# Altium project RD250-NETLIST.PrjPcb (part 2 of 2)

## Sheet 5.SchDoc
size 599 x 434 mm
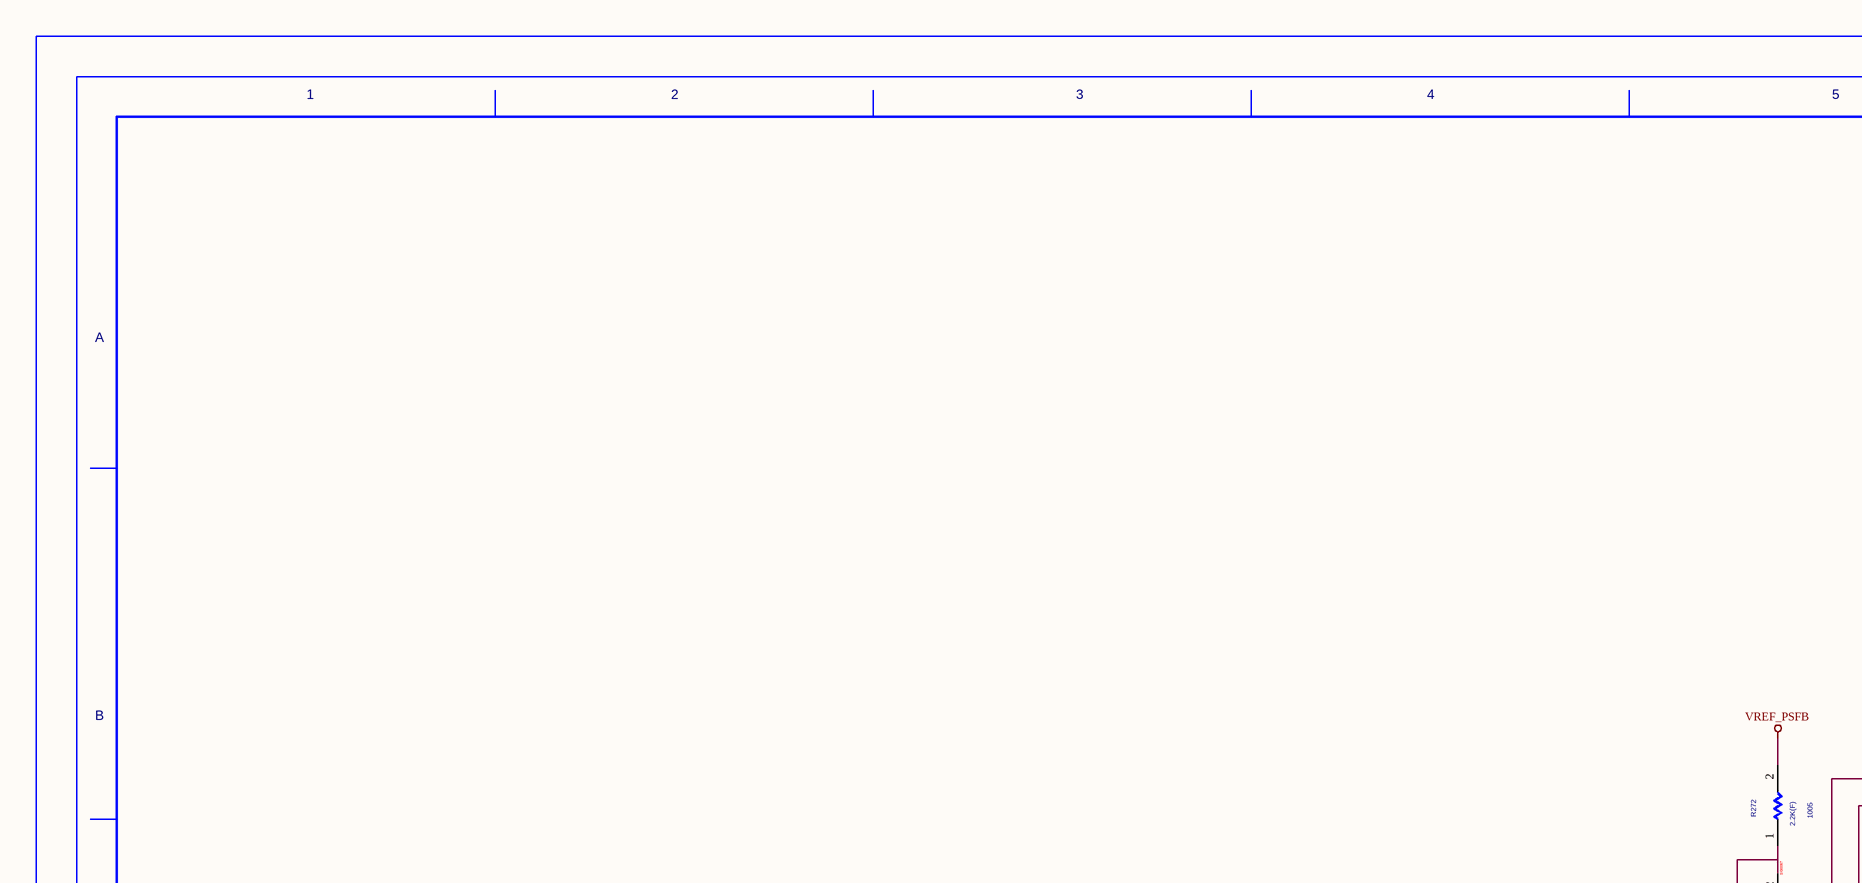
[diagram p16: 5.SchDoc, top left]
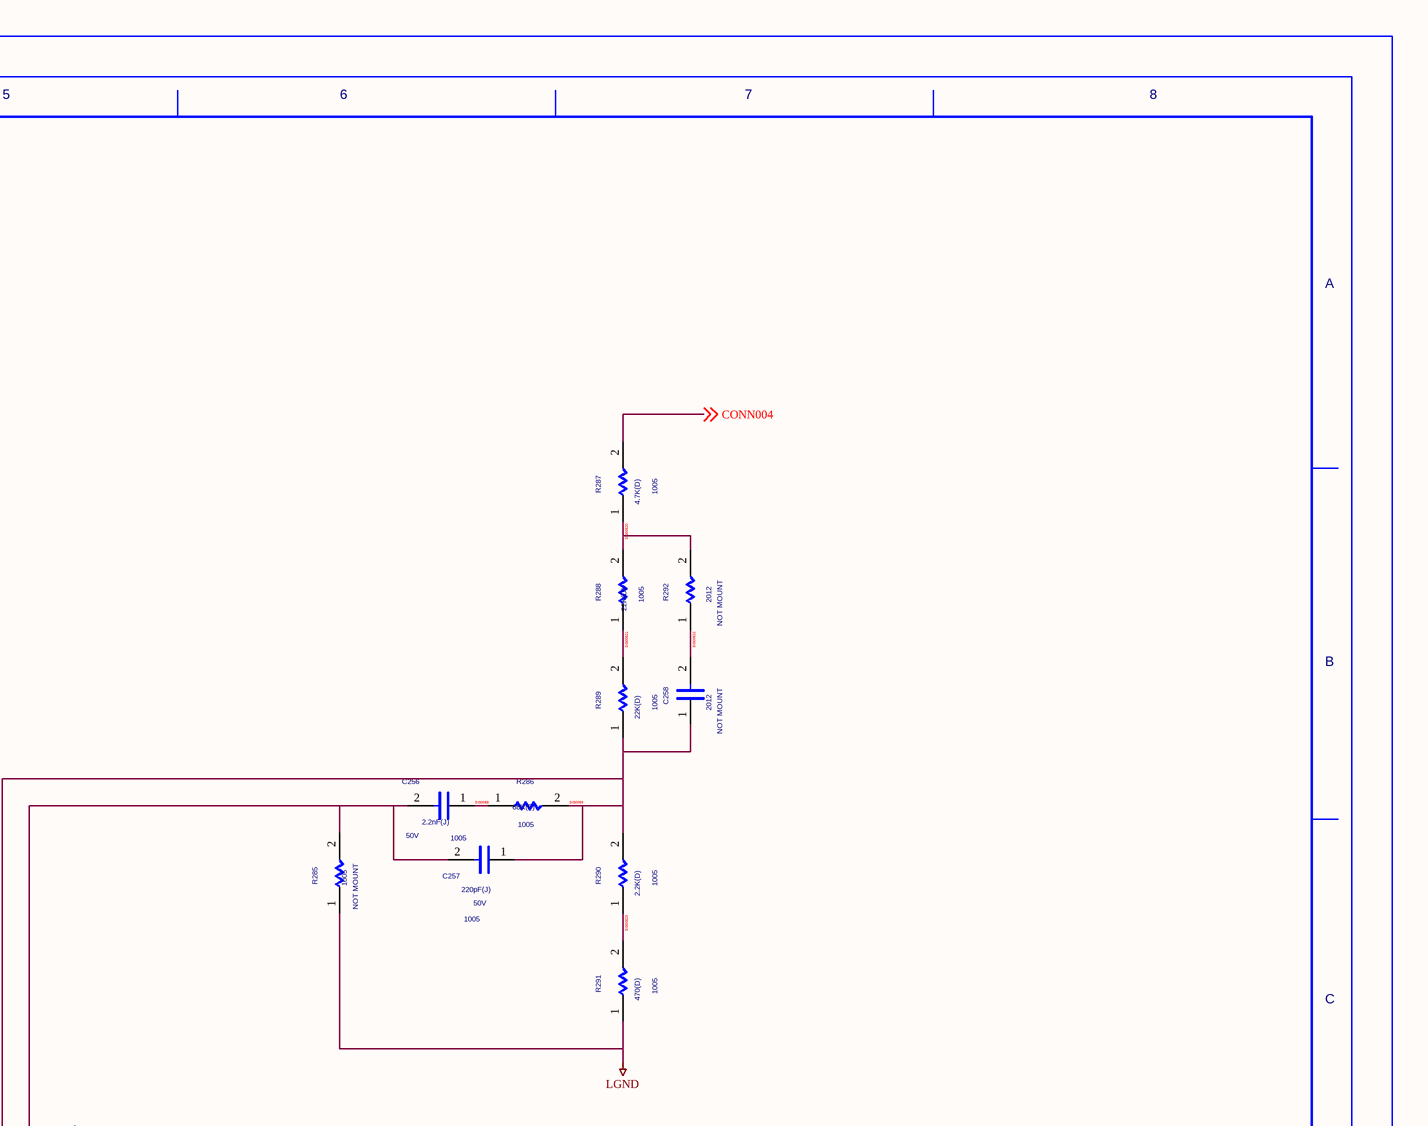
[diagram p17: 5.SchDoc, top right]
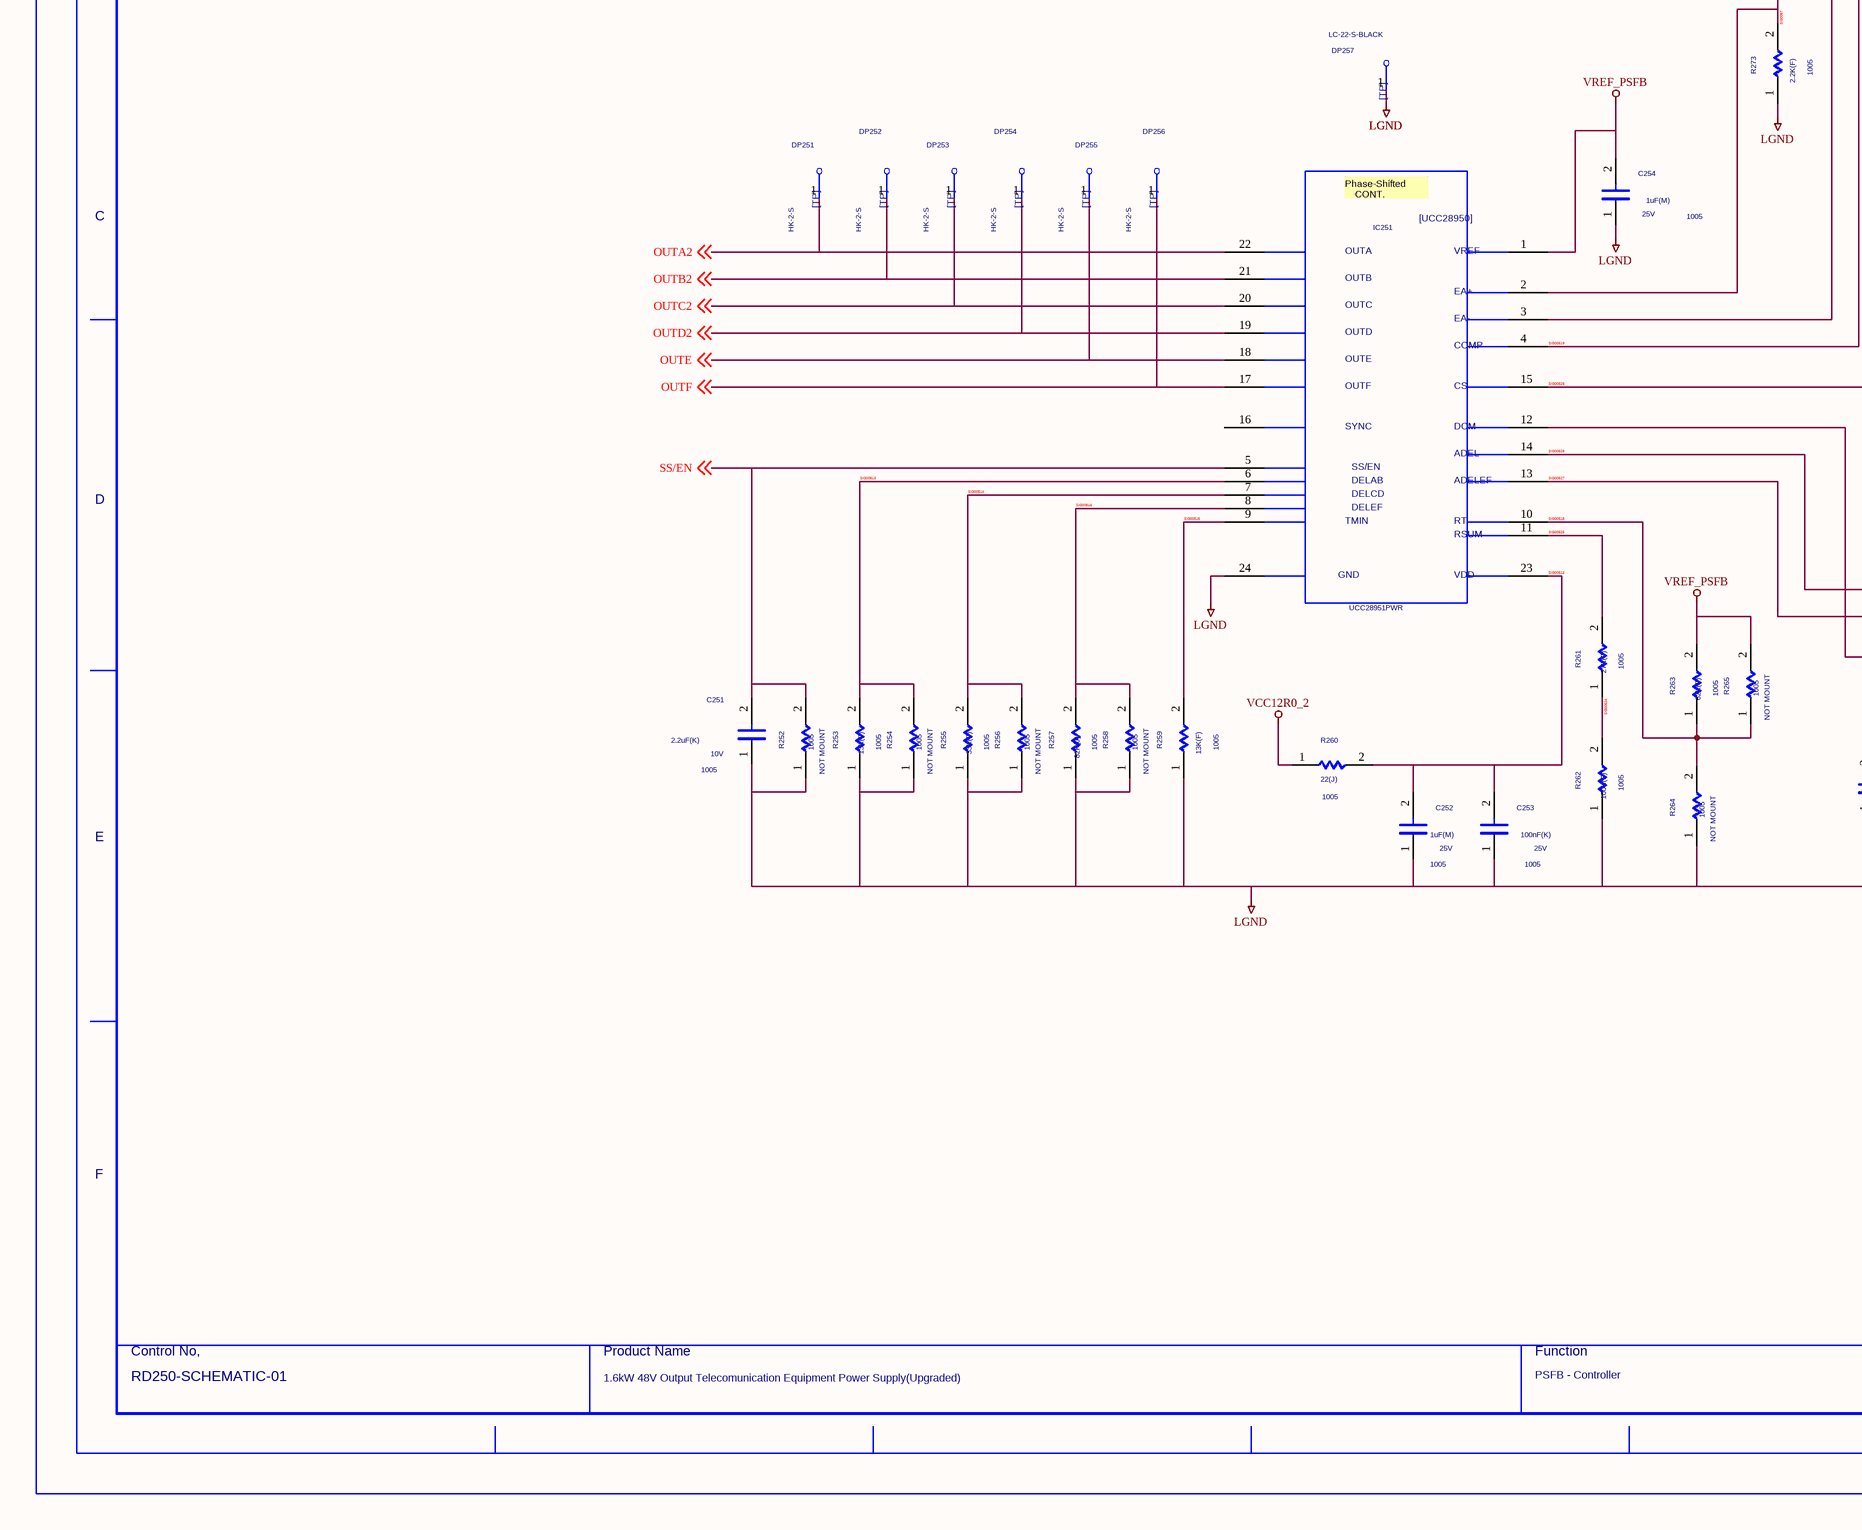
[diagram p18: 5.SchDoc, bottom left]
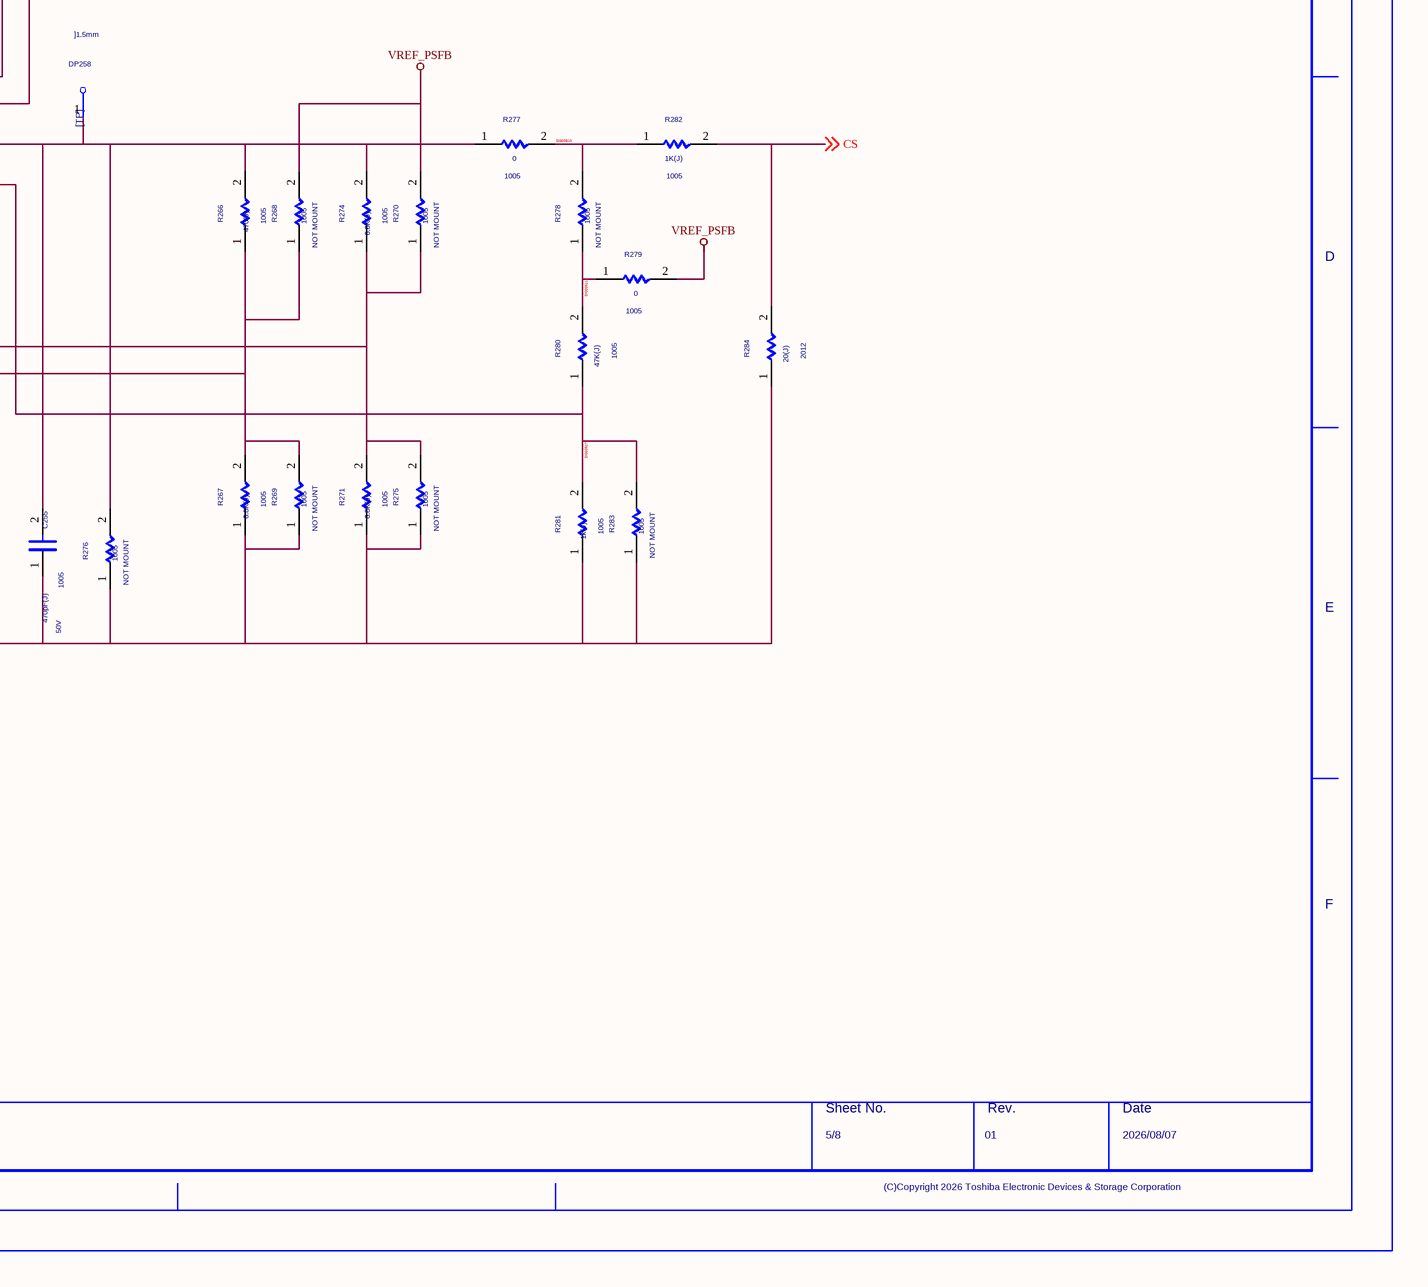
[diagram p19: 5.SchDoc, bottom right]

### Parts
(Parts that share a designator on the sheet are numbered #1, #2 ... from top to bottom, then left to right.)
C251  VAL1: 2.2uF(K)  VAL2: 10V  SIZECODESMD: 1005  (hidden comment: C)
C252  VAL1: 1uF(M)  VAL2: 25V  SIZECODESMD: 1005  (hidden comment: C)
C253  VAL1: 100nF(K)  VAL2: 25V  SIZECODESMD: 1005  (hidden comment: C)
C254  VAL1: 1uF(M)  VAL2: 25V  SIZECODESMD: 1005  (hidden comment: C)
C255  VAL1: 470pF(J)  VAL2: 50V  SIZECODESMD: 1005  (hidden comment: C)
C256  VAL1: 2.2nF(J)  VAL2: 50V  SIZECODESMD: 1005  (hidden comment: C)
C257  VAL1: 220pF(J)  VAL2: 50V  SIZECODESMD: 1005  (hidden comment: C)
C258  NOTMOUNT: NOT MOUNT  SIZECODESMD: 2012  (hidden comment: C)
DP251  VAL3: HK-2-S  (hidden comment: TP)
DP252  VAL3: HK-2-S  (hidden comment: TP)
DP253  VAL3: HK-2-S  (hidden comment: TP)
DP254  VAL3: HK-2-S  (hidden comment: TP)
DP255  VAL3: HK-2-S  (hidden comment: TP)
DP256  VAL3: HK-2-S  (hidden comment: TP)
DP257  VAL3: LC-22-S-BLACK  (hidden comment: TP)
DP258  USERCOMPTEXT1: ]1.5mm  (hidden comment: TP)
IC251  VAL3: UCC28951PWR  (hidden comment: L28950)
R252  NOTMOUNT: NOT MOUNT  SIZECODESMD: 1005  (hidden comment: R)
R253  VAL1: 13K(F)  SIZECODESMD: 1005  (hidden comment: R)
R254  NOTMOUNT: NOT MOUNT  SIZECODESMD: 1005  (hidden comment: R)
R255  VAL1: 33K(F)  SIZECODESMD: 1005  (hidden comment: R)
R256  NOTMOUNT: NOT MOUNT  SIZECODESMD: 1005  (hidden comment: R)
R257  VAL1: 82K(J)  SIZECODESMD: 1005  (hidden comment: R)
R258  NOTMOUNT: NOT MOUNT  SIZECODESMD: 1005  (hidden comment: R)
R259  VAL1: 13K(F)  SIZECODESMD: 1005  (hidden comment: R)
R260  VAL1: 22(J)  SIZECODESMD: 1005  (hidden comment: R)
R261  VAL1: 27K(F)  SIZECODESMD: 1005  (hidden comment: R)
R262  VAL1: 100K(F)  SIZECODESMD: 1005  (hidden comment: R)
R263  VAL1: 62K(F)  SIZECODESMD: 1005  (hidden comment: R)
R264  NOTMOUNT: NOT MOUNT  SIZECODESMD: 1005  (hidden comment: R)
R265  NOTMOUNT: NOT MOUNT  SIZECODESMD: 1005  (hidden comment: R)
R266  VAL1: 470(J)  SIZECODESMD: 1005  (hidden comment: R)
R267  VAL1: 6.8K(J)  SIZECODESMD: 1005  (hidden comment: R)
R268  NOTMOUNT: NOT MOUNT  SIZECODESMD: 1005  (hidden comment: R)
R269  NOTMOUNT: NOT MOUNT  SIZECODESMD: 1005  (hidden comment: R)
R270  NOTMOUNT: NOT MOUNT  SIZECODESMD: 1005  (hidden comment: R)
R271  VAL1: 6.8K(J)  SIZECODESMD: 1005  (hidden comment: R)
R272  VAL1: 2.2K(F)  SIZECODESMD: 1005  (hidden comment: R)
R273  VAL1: 2.2K(F)  SIZECODESMD: 1005  (hidden comment: R)
R274  VAL1: 6.8K(J)  SIZECODESMD: 1005  (hidden comment: R)
R275  NOTMOUNT: NOT MOUNT  SIZECODESMD: 1005  (hidden comment: R)
R276  NOTMOUNT: NOT MOUNT  SIZECODESMD: 1005  (hidden comment: R)
R277  VAL1: 0  SIZECODESMD: 1005  (hidden comment: R)
R278  NOTMOUNT: NOT MOUNT  SIZECODESMD: 1005  (hidden comment: R)
R279  VAL1: 0  SIZECODESMD: 1005  (hidden comment: R)
R280  VAL1: 47K(J)  SIZECODESMD: 1005  (hidden comment: R)
R281  VAL1: 1k(J)  SIZECODESMD: 1005  (hidden comment: R)
R282  VAL1: 1K(J)  SIZECODESMD: 1005  (hidden comment: R)
R283  NOTMOUNT: NOT MOUNT  SIZECODESMD: 1005  (hidden comment: R)
R284  VAL1: 20(J)  SIZECODESMD: 2012  (hidden comment: R)
R285  NOTMOUNT: NOT MOUNT  SIZECODESMD: 1005  (hidden comment: R)
R286  VAL1: 68K(F)  SIZECODESMD: 1005  (hidden comment: R)
R287  VAL1: 4.7K(D)  SIZECODESMD: 1005  (hidden comment: R)
R288  VAL1: 22K(D)  SIZECODESMD: 1005  (hidden comment: R)
R289  VAL1: 22K(D)  SIZECODESMD: 1005  (hidden comment: R)
R290  VAL1: 2.2K(D)  SIZECODESMD: 1005  (hidden comment: R)
R291  VAL1: 470(D)  SIZECODESMD: 1005  (hidden comment: R)
R292  NOTMOUNT: NOT MOUNT  SIZECODESMD: 2012  (hidden comment: R)
U?#5  DATE: 2026/08/07  DRAWINGNUMBER: RD250-SCHEMATIC-01  TITLE: 1.6kW 48V Output Telecomunication / Equipment Power Supply(Upgraded)  FUNCTION: PSFB - Controller  SHEETNUMBER: 5/8  REVISION: 01  (hidden comment: WAKU_A3_TDSC_PSDEV_LOCAL)

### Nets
LGND: C251.1 C252.1 C253.1 C254.1 C255.1 DP257.1 IC251.24 R252.1 R253.1 R254.1 R255.1 R256.1 R257.1 R258.1 R259.1 R262.1 R264.1 R267.1 R269.1 R271.1 R273.1 R275.1 R276.1 R281.1 R283.1 R284.1 R285.1 R291.1
VCC12R0_2: R260.1
VREF_PSFB: C254.2 IC251.1 R263.2 R265.2 R268.2 R270.2 R272.2 R279.2
CONN004: R287.2 ; off-sheet CONN004
CS: R282.2 R284.2 ; off-sheet CS
OUTA2: DP251.1 IC251.22 ; off-sheet OUTA2
OUTB2: DP252.1 IC251.21 ; off-sheet OUTB2
OUTC2: DP253.1 IC251.20 ; off-sheet OUTC2
OUTD2: DP254.1 IC251.19 ; off-sheet OUTD2
OUTE: DP255.1 IC251.18 ; off-sheet OUTE
OUTF: DP256.1 IC251.17 ; off-sheet OUTF
SIG0057: IC251.2 R272.1 R273.2
SIG0058: C256.1 R286.1
SIG0059: C257.1 C258.1 IC251.3 R286.2 R289.1 R290.2
SIG00510: R277.2 R278.2 R282.1
SIG00511: R278.1 R279.1 R280.2
SIG00512: C252.2 C253.2 IC251.23 R260.2
SIG00513: IC251.6 R253.2 R254.2
SIG00514: IC251.7 R255.2 R256.2
SIG00515: IC251.9 R259.2
SIG00516: IC251.8 R257.2 R258.2
SIG00517: IC251.12 R280.1 R281.2 R283.2
SIG00518: IC251.10 R263.1 R264.2 R265.1
SIG00519: C256.2 C257.2 IC251.4 R285.2
SIG00520: R287.1 R288.2 R292.2
SIG00521: R288.1 R289.2
SIG00522: C258.2 R292.1
SIG00523: R290.1 R291.2
SIG00524: R261.1 R262.2
SIG00525: IC251.11 R261.2
SIG00526: C255.2 DP258.1 IC251.15 R266.2 R274.2 R276.2 R277.1
SIG00527: IC251.13 R266.1 R267.2 R268.1 R269.2
SIG00528: IC251.14 R270.1 R271.2 R274.1 R275.2
SS/EN: C251.2 IC251.5 R252.2 ; off-sheet SS/EN

Not connected (* = marked no-connect by the designer): IC251 16

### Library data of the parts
C251-C255 = C_Dup1: OriginalSymbolOrigin: (2540,7620); COMP: PRT_52; MAXGCOUNT: 1; SAVECOUNT: 0
C256 = C_Dup1: SQ_PART_MODEL: CON_5.6N; OriginalSymbolOrigin: (2540,7620); COMP: PRT_52; MAXGCOUNT: 1; ADSCNVFLAG: ON; ADSCOMPONENTNAME: C_1005; SAVECOUNT: 0
C257 = C_Dup1: SQ_PART_MODEL: CON_560P; OriginalSymbolOrigin: (2540,7620); COMP: PRT_52; MAXGCOUNT: 1; ADSCNVFLAG: ON; ADSCOMPONENTNAME: C_1005; SAVECOUNT: 0
C258 = C_Dup1: OriginalSymbolOrigin: (2540,7620); COMP: C2012; CHIPSIZE: 3216; MAXGCOUNT: 1; SAVECOUNT: 0
DP251-DP256 = TP: TIME: 16:12:21; UPDATEUSER: fukuda-y; UPDATETIME: 16:18:11; SAVECOUNT: 2; SAVEAREA0: -242,-92,12810,7836; OriginalSymbolOrigin: (0,7620); COMP: PRT_44
DP257 = TP: TIME: 16:12:21; UPDATEUSER: fukuda-y; UPDATETIME: 16:18:11; SAVECOUNT: 2; SAVEAREA0: -242,-92,12810,7836; OriginalSymbolOrigin: (0,7620); COMP: PRT_34
DP258 = TP: TIME: 16:12:21; UPDATEUSER: fukuda-y; UPDATETIME: 16:18:11; SAVECOUNT: 2; SAVEAREA0: -242,-92,12810,7836; OriginalSymbolOrigin: (0,7620); COMP: DTP815
IC251 = L28950: SAVEAREA0: -25263,1478,86635,87004; SAVECOUNT: 35; TIME: 15:02:55; UPDATEUSER: cae; UPDATETIME: 16:32:09; OriginalSymbolOrigin: (7620,83820); COMP: PRT_16
R252 R254 R256 R258 R264 R265 R269 R275 R276 R278 R283 R285 = R_Dup1: OriginalSymbolOrigin: (5080,5080); COMP: GDM010004481; CHIPSIZE: 1608; MAXGCOUNT: 1; SAVECOUNT: 0
R253 R255 R257 R260-R263 R267 R271-R273 R280-R282 R286-R291 = R_Dup1: VAL2: 63mW; OriginalSymbolOrigin: (5080,5080); COMP: GDM010004481; CHIPSIZE: 1608; MAXGCOUNT: 1; SAVECOUNT: 0
R259 = R_Dup1: SQ_PART_MODEL: RES_15K; VAL2: 63mW; OriginalSymbolOrigin: (5080,5080); COMP: GDM010004481; CHIPSIZE: 1608; MAXGCOUNT: 1; ADSCNVFLAG: ON; ADSCOMPONENTNAME: R_1608; SAVECOUNT: 0
R266 R274 = R_Dup1: VAL2: 63mW; OriginalSymbolOrigin: (5080,5080); COMP: GDM010004481; CHIPSIZE: 1608; MAXGCOUNT: 1; ADSCOMPONENTNAME: R_1005; SAVECOUNT: 0
R268 R270 = R_Dup1: OriginalSymbolOrigin: (5080,5080); COMP: GDM010004481; CHIPSIZE: 1608; MAXGCOUNT: 1; ADSCOMPONENTNAME: R_1005; SAVECOUNT: 0
R277 = R_Dup1: SQ_PART_MODEL: RES_0; VAL2: 63mW; OriginalSymbolOrigin: (5080,5080); COMP: GDM010004481; CHIPSIZE: 1608; MAXGCOUNT: 1; ADSCNVFLAG: ON; ADSCOMPONENTNAME: R_1608
R279 = R_Dup1: VAL2: 63mW; OriginalSymbolOrigin: (5080,5080); COMP: GDM010004481; CHIPSIZE: 1608; MAXGCOUNT: 1
R284 = R_Dup1: VAL2: 250mW; OriginalSymbolOrigin: (5080,5080); COMP: R2012; CHIPSIZE: 3216; MAXGCOUNT: 1; SAVECOUNT: 0
R292 = R_Dup1: OriginalSymbolOrigin: (5080,5080); COMP: R2012; CHIPSIZE: 3216; MAXGCOUNT: 1; SAVECOUNT: 0
U?#5 = WAKU_A3_TDSC_PSDEV_LOCAL: PLOTTIME: HH:MM; SAVEAREA0: -311037,-554865,914355,115662; TIME: 16:14:05; UPDATEUSER: t5459927; UPDATETIME: 17:59:50; SAVECOUNT: 3; ZONEOFFSETX: 36; ZONEOFFSETY: -24; OriginalSymbolOrigin: (0,434340); SHTSAVECOUNT: 108; PAGENUMBER: 5; DESIGNED: TOSHIBA

## Sheet 6.SchDoc
size 599 x 434 mm
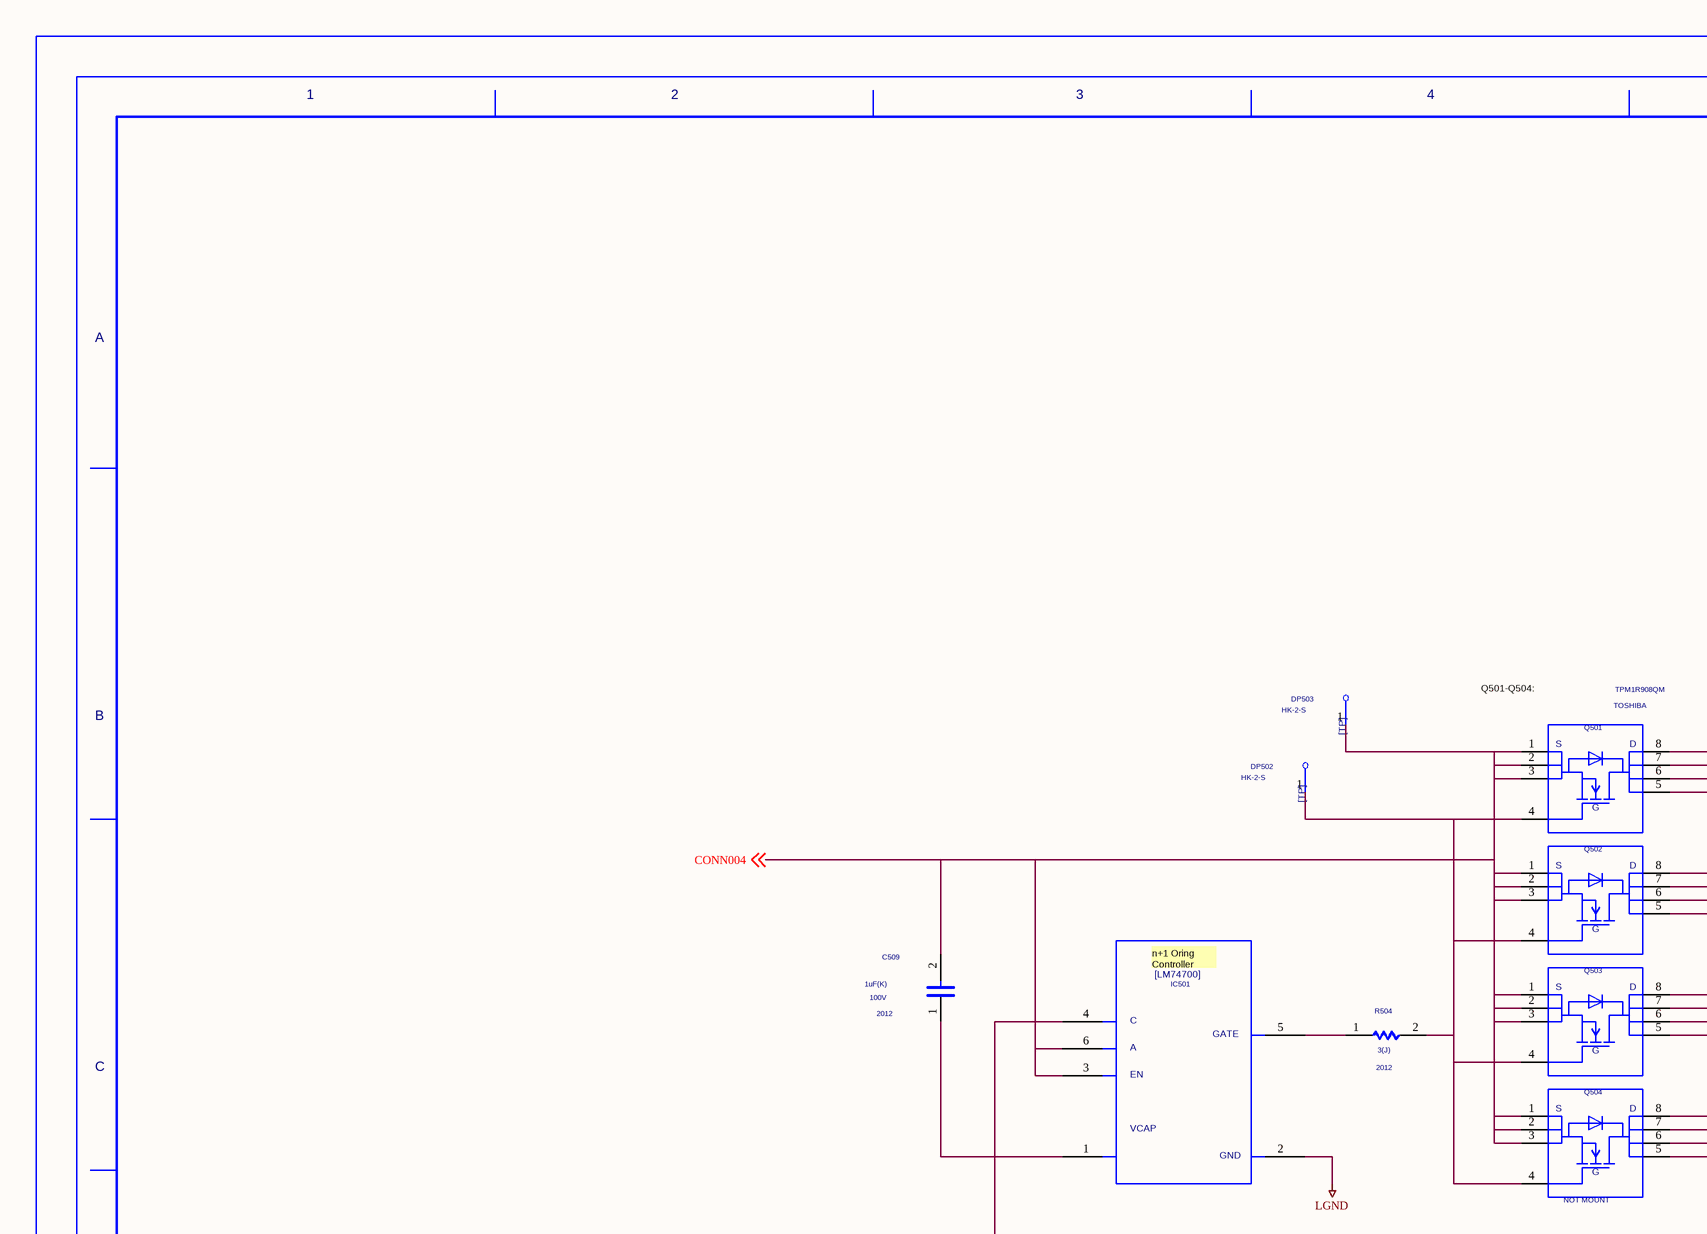
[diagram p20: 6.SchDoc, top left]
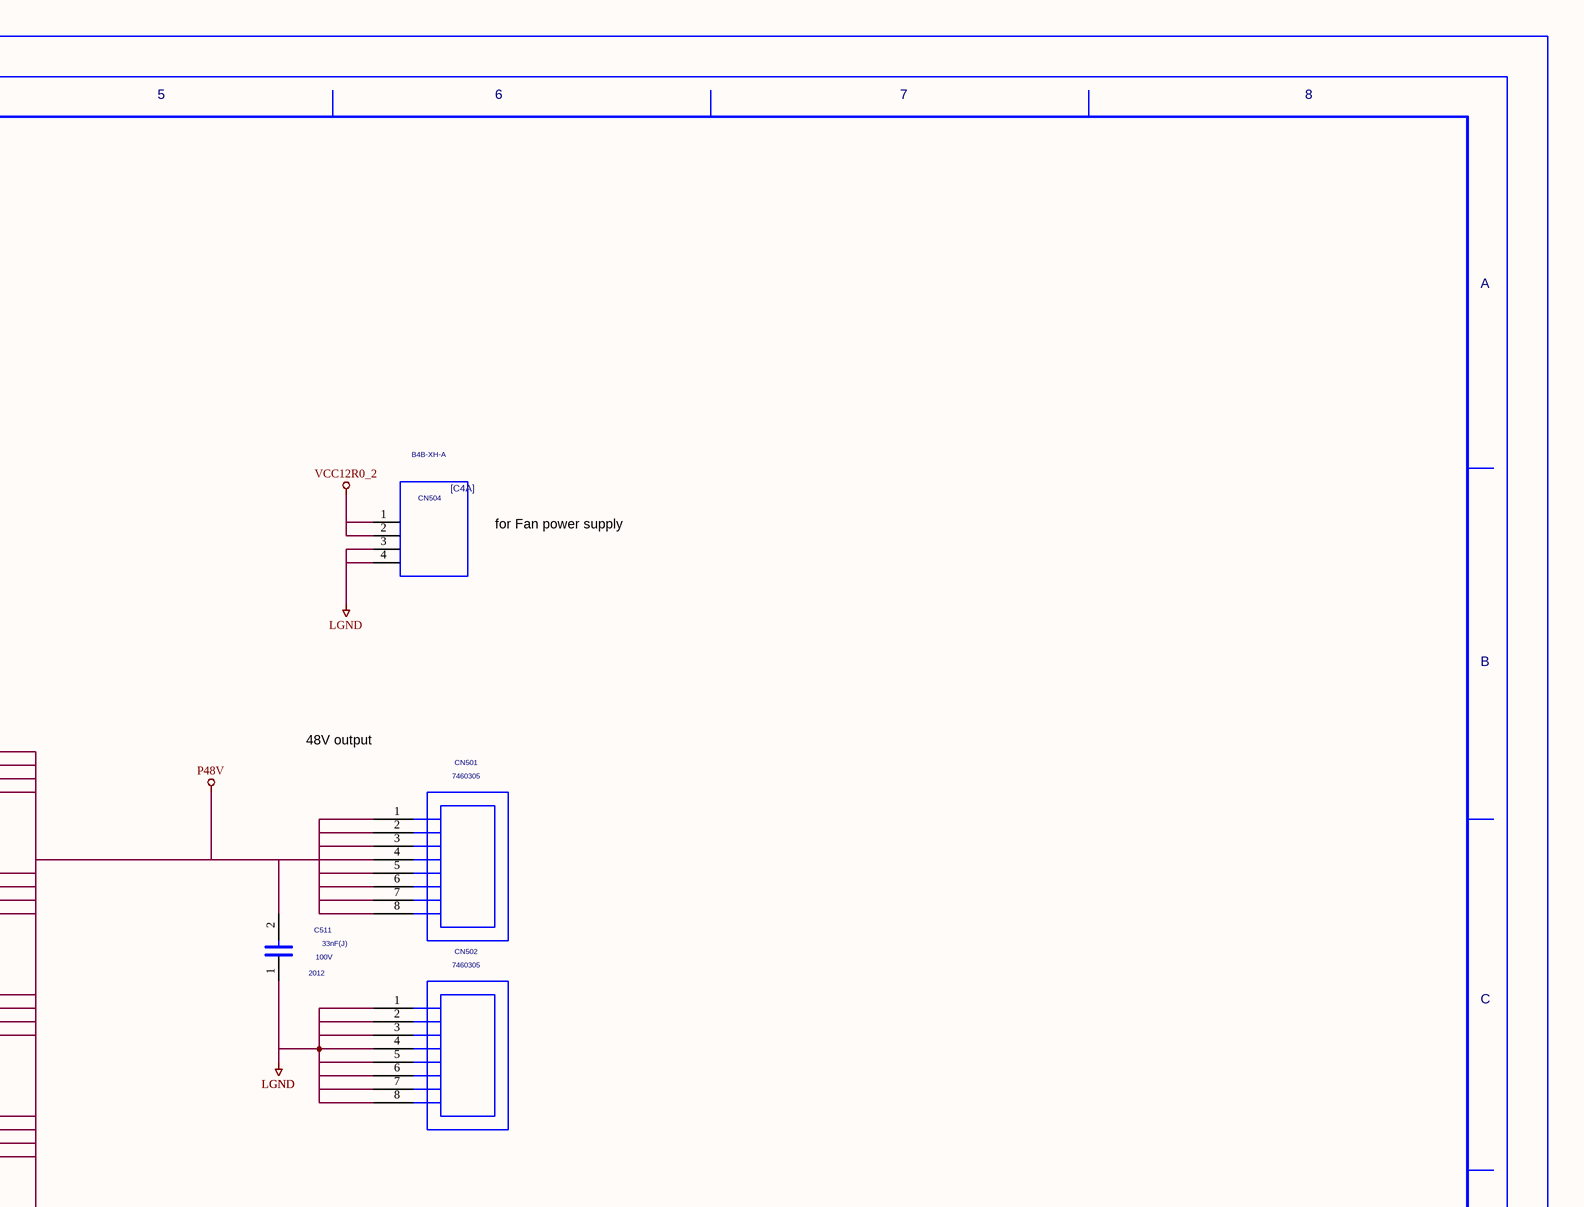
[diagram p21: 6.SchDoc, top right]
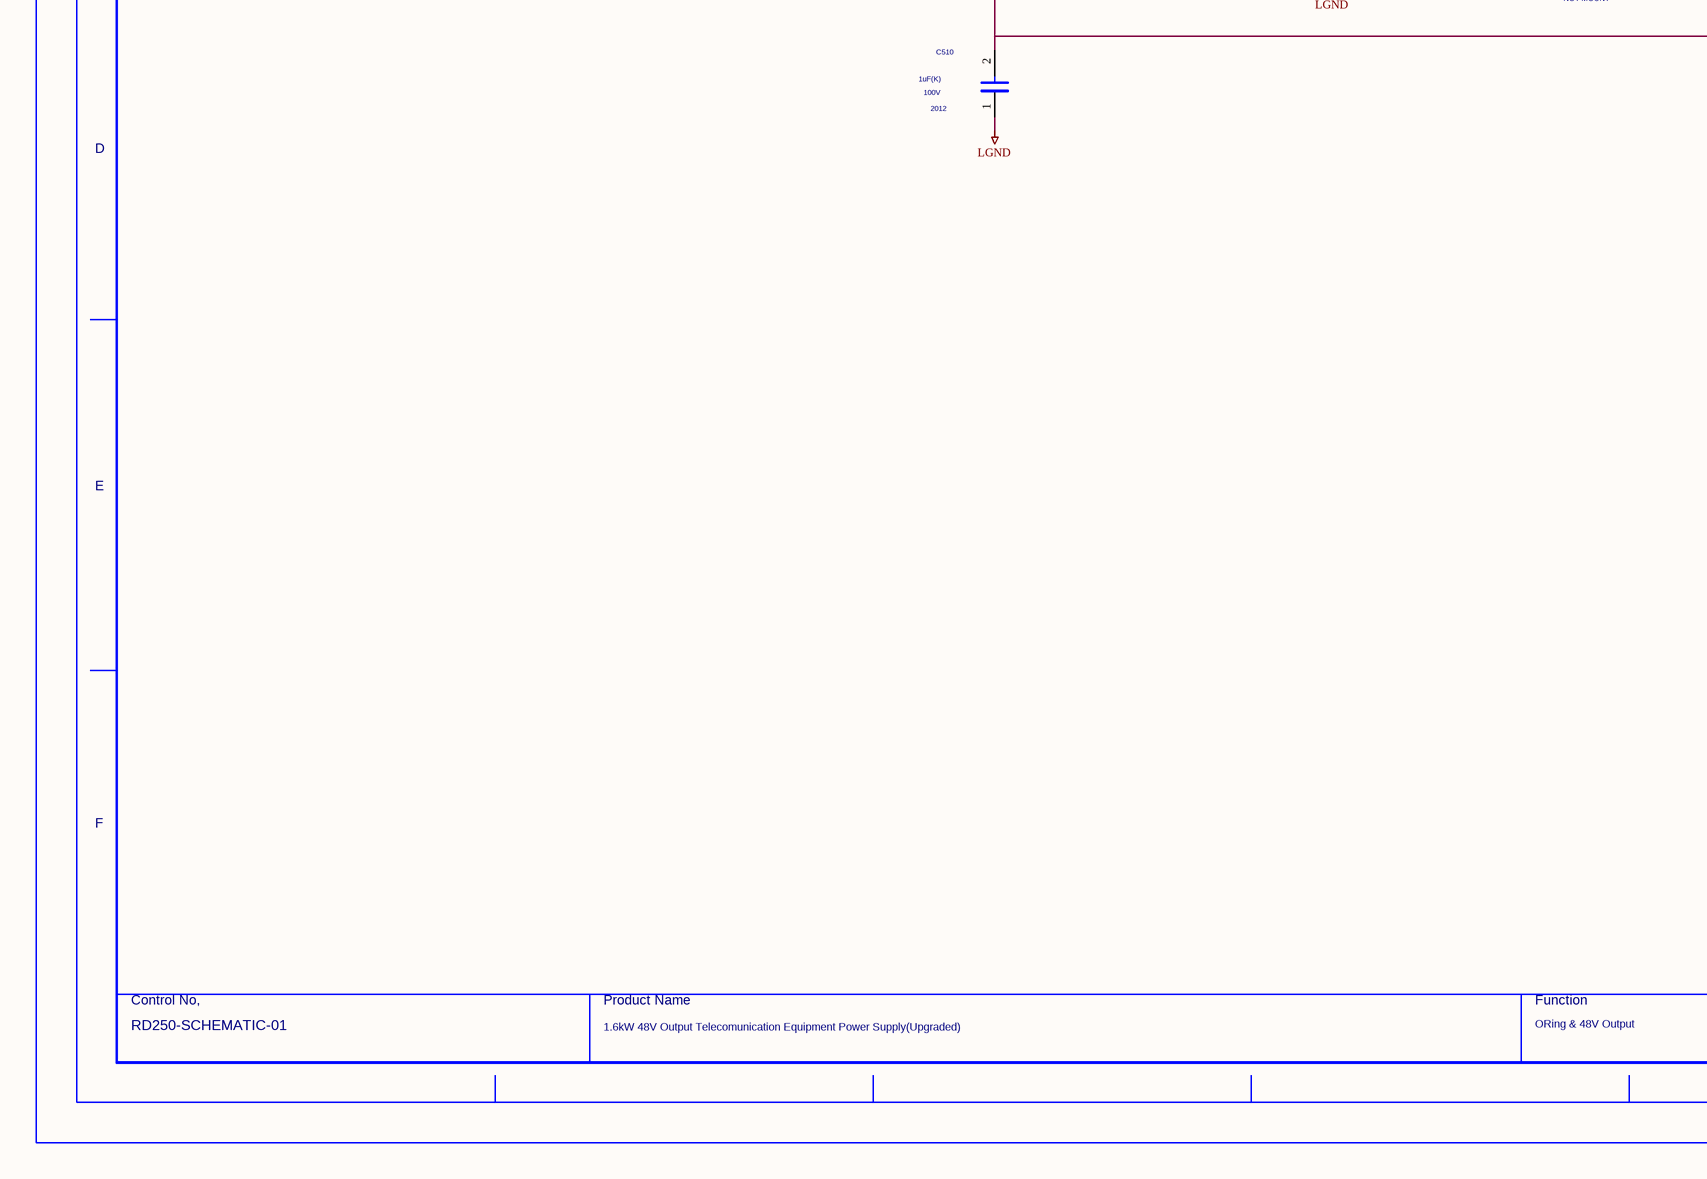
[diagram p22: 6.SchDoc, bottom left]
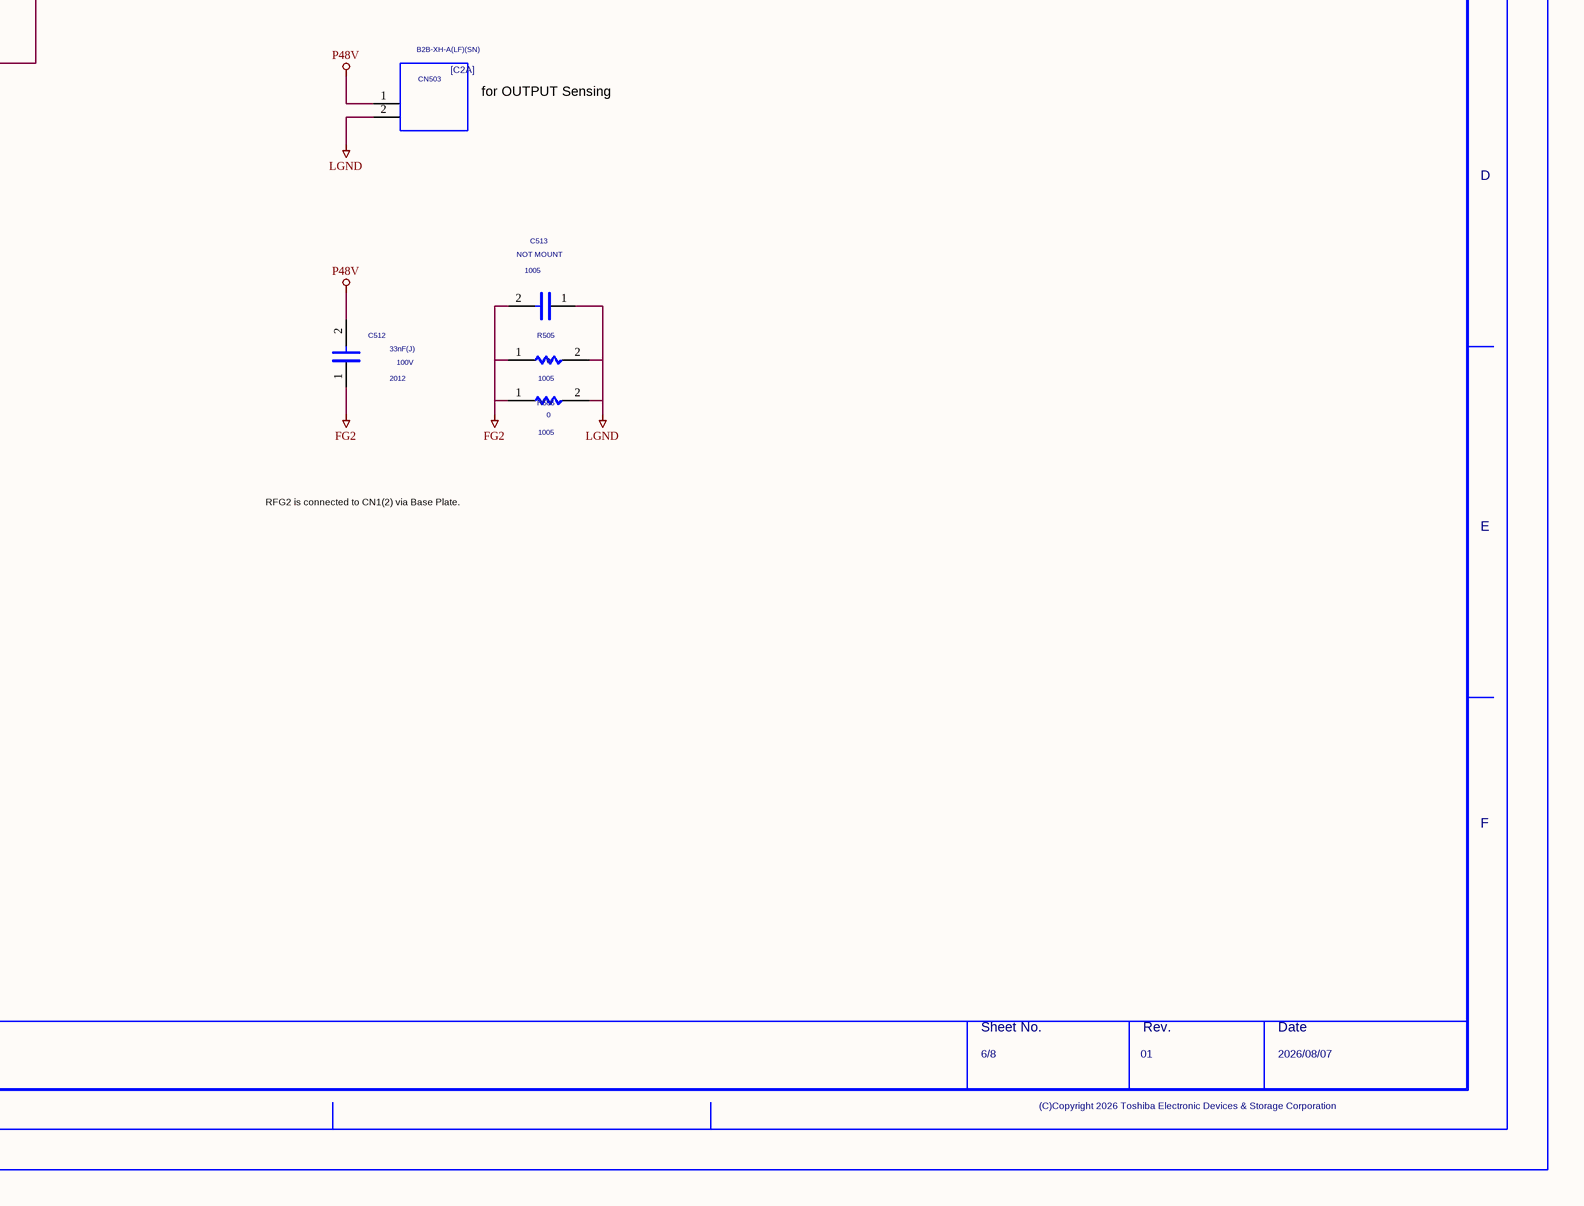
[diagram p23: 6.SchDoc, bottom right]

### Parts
(Parts that share a designator on the sheet are numbered #1, #2 ... from top to bottom, then left to right.)
C509  VAL1: 1uF(K)  VAL2: 100V  SIZECODESMD: 2012  (hidden comment: GRM21BC71E106KE01)
C510  VAL1: 1uF(K)  VAL2: 100V  SIZECODESMD: 2012  (hidden comment: GRM21BC71E106KE01)
C511  VAL1: 33nF(J)  VAL2: 100V  SIZECODESMD: 2012  (hidden comment: GRM21BC71E106KE01)
C512  VAL1: 33nF(J)  VAL2: 100V  SIZECODESMD: 2012  (hidden comment: GRM21BC71E106KE01)
C513  NOTMOUNT: NOT MOUNT  SIZECODESMD: 1005  (hidden comment: C)
CN501  7460305
CN502  7460305
CN503  VAL3: B2B-XH-A(LF)(SN)  (hidden comment: C2A)
CN504  VAL3: B4B-XH-A  (hidden comment: C4A)
DP502  VAL3: HK-2-S  (hidden comment: TP)
DP503  VAL3: HK-2-S  (hidden comment: TP)
IC501  LM74700-Q1  (value not drawn)
Q501  VAL3: TPM1R908QM  USERCOMPTEXT3: TOSHIBA  (hidden comment: NCHMOSFET_SOPADVANCE-E-01)
Q502  NCHMOSFET_SOPADVANCE-E-01  (value not drawn)
Q503  NCHMOSFET_SOPADVANCE-E-01  (value not drawn)
Q504  NOTMOUNT: NOT MOUNT  (hidden comment: NCHMOSFET_SOPADVANCE-E-01)
R504  VAL1: 3(J)  SIZECODESMD: 2012  (hidden comment: R)
R505  VAL1: 0  SIZECODESMD: 1005  (hidden comment: R)
R506  VAL1: 0  SIZECODESMD: 1005  (hidden comment: R)
U?#6  DATE: 2026/08/07  DRAWINGNUMBER: RD250-SCHEMATIC-01  TITLE: 1.6kW 48V Output Telecomunication / Equipment Power Supply(Upgraded)  FUNCTION: ORing & 48V Output  SHEETNUMBER: 6/8  REVISION: 01  (hidden comment: WAKU_A3_TDSC_PSDEV_LOCAL)

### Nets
FG2: C512.1 C513.2 R505.1 R506.1
LGND: C510.1 C511.1 C513.1 CN502.1 CN502.2 CN502.3 CN502.4 CN502.5 CN502.6 CN502.7 CN502.8 CN503.2 CN504.3 CN504.4 IC501.2 R505.2 R506.2
P48V: C510.2 C511.2 C512.2 CN501.1 CN501.2 CN501.3 CN501.4 CN501.5 CN501.6 CN501.7 CN501.8 CN503.1 IC501.4 Q501.5 Q501.6 Q501.7 Q501.8 Q502.5 Q502.6 Q502.7 Q502.8 Q503.5 Q503.6 Q503.7 Q503.8 Q504.5 Q504.6 Q504.7 Q504.8
VCC12R0_2: CN504.1 CN504.2
CONN004: C509.2 DP503.1 IC501.3 IC501.6 Q501.1 Q501.2 Q501.3 Q502.1 Q502.2 Q502.3 Q503.1 Q503.2 Q503.3 Q504.1 Q504.2 Q504.3 ; off-sheet CONN004
SIG122: C509.1 IC501.1
SIG136: IC501.5 R504.1
SIG141: DP502.1 Q501.4 Q502.4 Q503.4 Q504.4 R504.2

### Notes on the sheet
- for Fan power supply
- Q501-Q504:
- 48V output
- for OUTPUT Sensing
- RFG2 is connected to CN1(2) via Base Plate.

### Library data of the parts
C509-C512 = GRM21BC71E106KE01: TIME: 10:25:11; UPDATEUSER: t4887876; UPDATETIME: 16:23:00; SAVECOUNT: 11; MAKER: Murata; OriginalSymbolOrigin: (2540,7620); CHIPSIZE: 1005; MAXGCOUNT: 1
C513 = C_Dup1: as C251-C255 on sheet 5
CN501 CN502 = 7460305: SAVEAREA0: -4578,-286,40174,28213; SAVECOUNT: 17; TIME: 14:53:12; UPDATEUSER: t4887876; UPDATETIME: 16:00:29; VAL2: 160Amax; VAL1: M5; OriginalSymbolOrigin: (7620,27940)
CN503 = C2A: OUMEPARTTYPE2: CN; SAVEAREA0: -4611,-206,24632,18258; SAVECOUNT: 25; TIME: 13:28:28; UPDATEUSER: tomizawa-y; UPDATETIME: 12:08:31; OriginalSymbolOrigin: (2540,15240); MAXGCOUNT: 1; COMP: K2203993; ADSCNVFLAG: ON
CN504 = C4A: SAVEAREA0: -8845,-265,28754,23475; SAVECOUNT: 22; TIME: 13:28:28; UPDATEUSER: tomizawa-y; UPDATETIME: 15:03:27; OriginalSymbolOrigin: (2540,20320); MAXGCOUNT: 1; COMP: K22S0019; ADSCNVFLAG: ON
DP502 DP503 = TP: as DP251-DP256 on sheet 5
IC501 = LM74700-Q1: SAVEAREA0: -16399,-622,62276,51274; TIME: 11:49:52; UPDATEUSER: t5459927; UPDATETIME: 12:54:53; SAVECOUNT: 39; OriginalSymbolOrigin: (7620,48260)
Q501 = NCHMOSFET_SOPADVANCE-E-01: TIME: 18:29:30; UPDATEUSER: t4887876; UPDATETIME: 14:15:50; SAVECOUNT: 31; SAVEAREA0: -10143,-336,37609,28718; COMP: NchMOSFET_SOPAdvance_E-01; VAL2: R・&¦#ﾐ{¦; CHIPSET: R獸¦#ﾐ{¦; OriginalSymbolOrigin: (5080,22860); MAXGCOUNT: 1
Q502-Q504 = NCHMOSFET_SOPADVANCE-E-01: TIME: 18:29:30; UPDATEUSER: t4887876; UPDATETIME: 14:15:50; SAVECOUNT: 31; SAVEAREA0: -10143,-336,37609,28718; COMP: NchMOSFET_SOPAdvance_E-01; VAL3: TPM1R908QM; VAL2: R・&¦#ﾐ{¦; CHIPSET: R獸¦#ﾐ{¦; OriginalSymbolOrigin: (5080,22860); MAXGCOUNT: 1; USERCOMPTEXT3: TOSHIBA
R504 = R_Dup1: VAL2: 250mW; OriginalSymbolOrigin: (5080,5080); COMP: R2012; CHIPSIZE: 1608; MAXGCOUNT: 1; SAVECOUNT: 0
R505 R506 = R_Dup1: as R279 on sheet 5
U?#6 = WAKU_A3_TDSC_PSDEV_LOCAL: PLOTTIME: HH:MM; SAVEAREA0: -311037,-554865,914355,115662; TIME: 12:01:09; UPDATEUSER: t5459927; UPDATETIME: 17:59:50; SAVECOUNT: 3; ZONEOFFSETX: 36; ZONEOFFSETY: -24; OriginalSymbolOrigin: (0,434340); SHTSAVECOUNT: 84; PAGENUMBER: 6; DESIGNED: TOSHIBA

## Sheet 7.SchDoc
size 599 x 434 mm
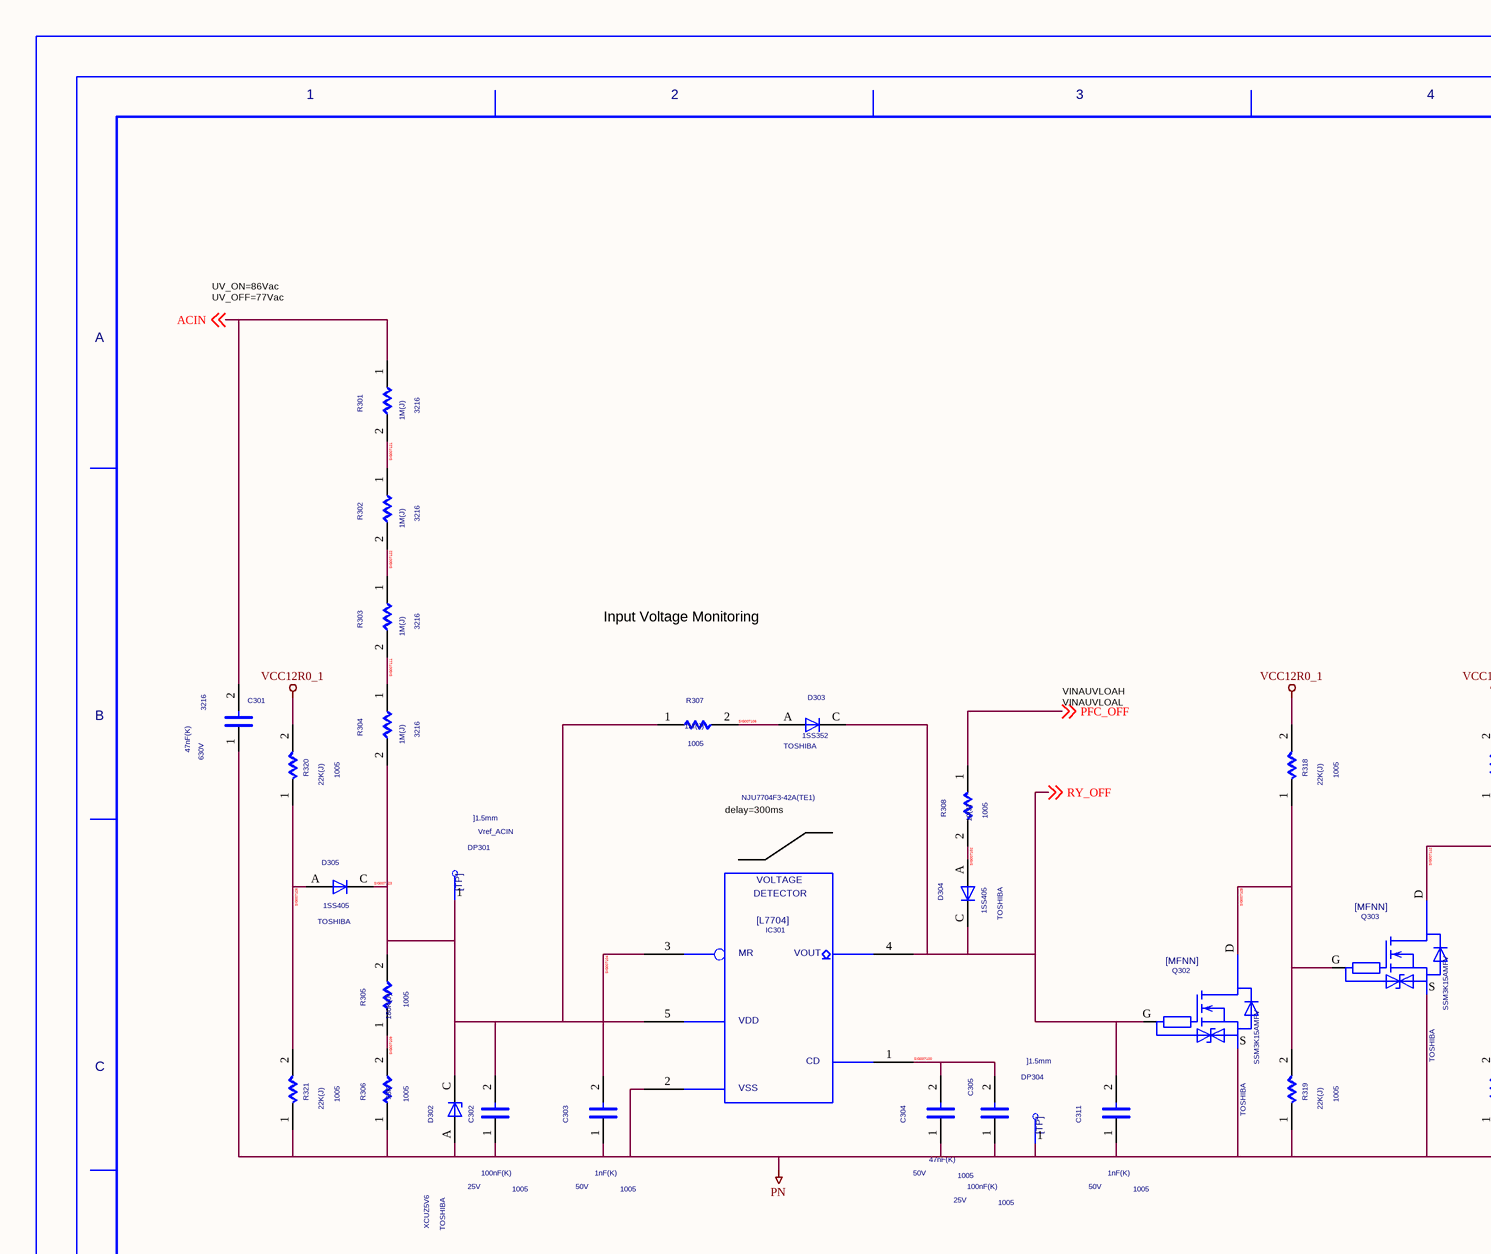
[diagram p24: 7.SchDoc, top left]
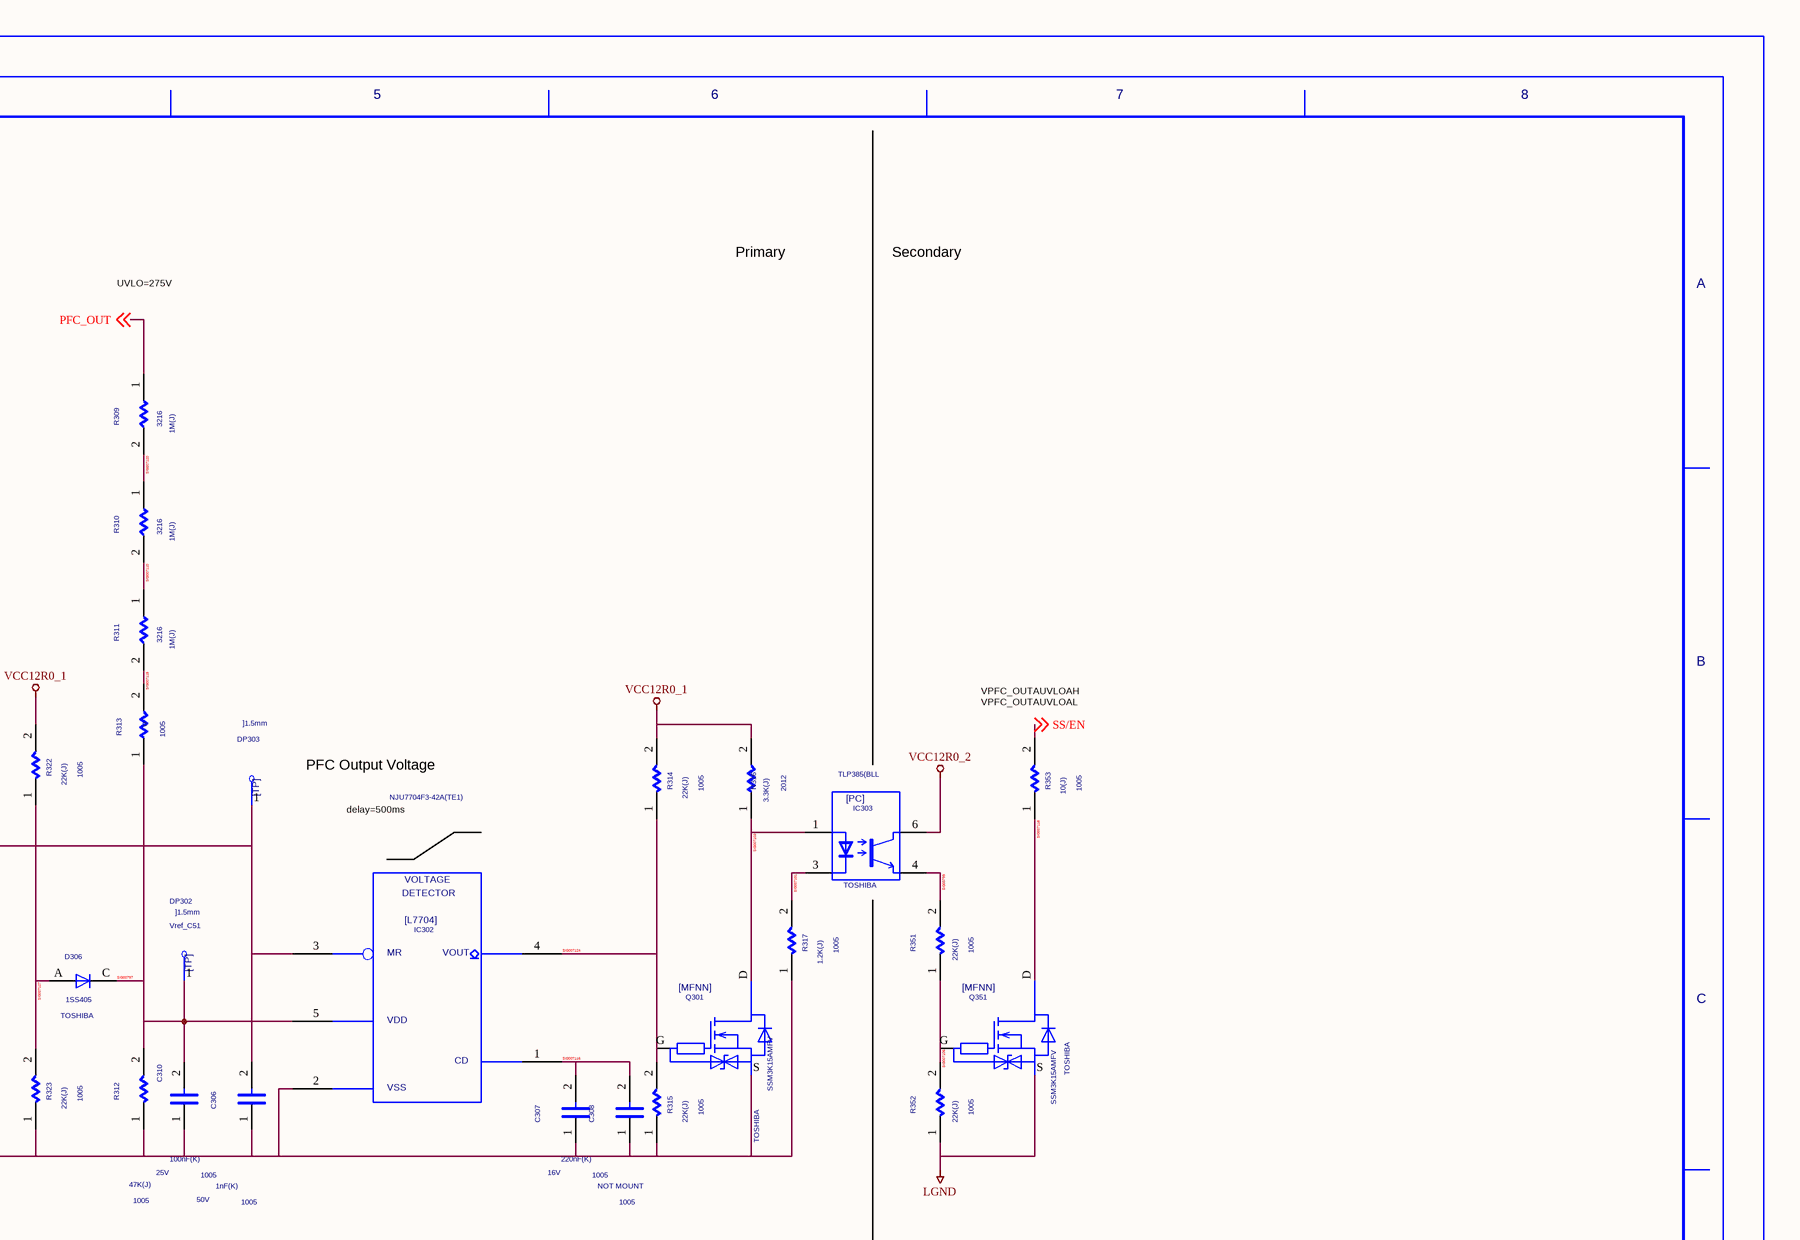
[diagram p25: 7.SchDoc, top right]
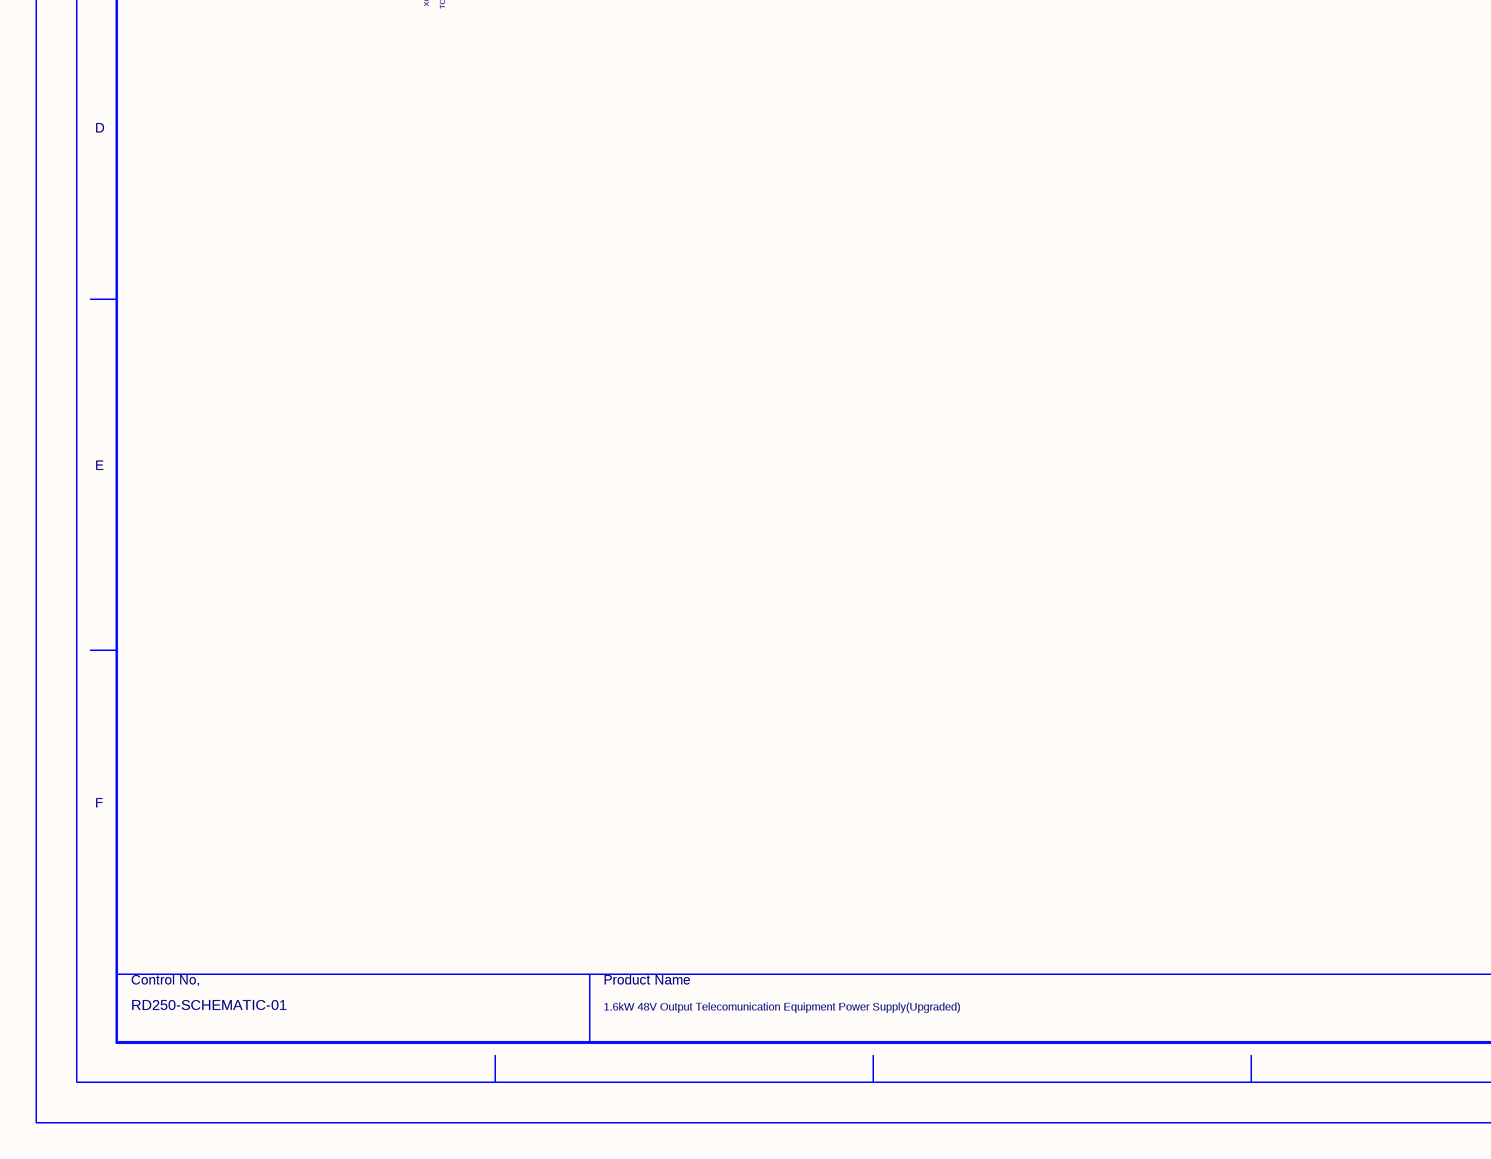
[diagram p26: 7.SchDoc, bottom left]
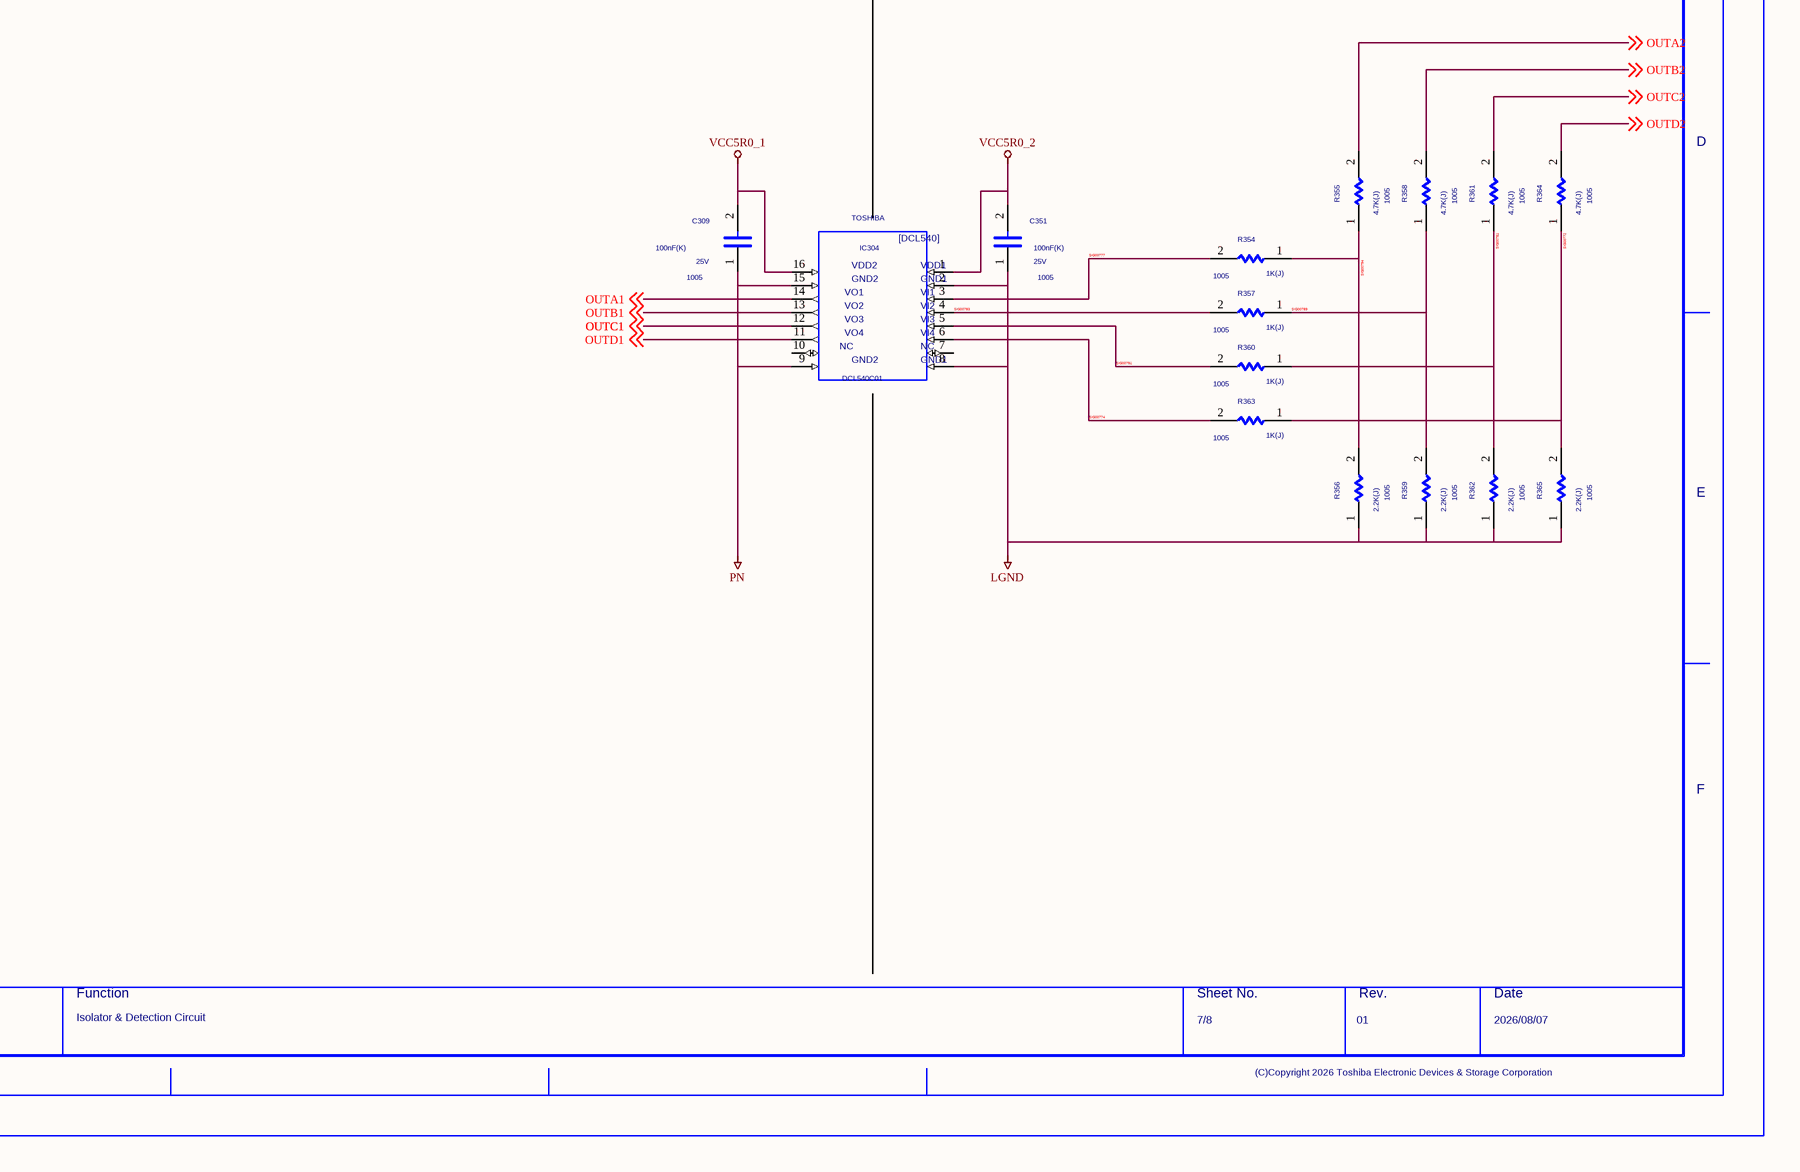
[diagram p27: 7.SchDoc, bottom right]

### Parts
(Parts that share a designator on the sheet are numbered #1, #2 ... from top to bottom, then left to right.)
C301  VAL1: 47nF(K)  VAL2: 630V  SIZECODESMD: 3216  (hidden comment: C)
C302  VAL1: 100nF(K)  VAL2: 25V  SIZECODESMD: 1005  (hidden comment: C)
C303  VAL1: 1nF(K)  VAL2: 50V  SIZECODESMD: 1005  (hidden comment: C)
C304  VAL1: 47nF(K)  VAL2: 50V  SIZECODESMD: 1005  (hidden comment: C)
C305  VAL1: 100nF(K)  VAL2: 25V  SIZECODESMD: 1005  (hidden comment: C)
C306  VAL1: 1nF(K)  VAL2: 50V  SIZECODESMD: 1005  (hidden comment: C)
C307  VAL1: 220nF(K)  VAL2: 16V  SIZECODESMD: 1005  (hidden comment: C)
C308  NOTMOUNT: NOT MOUNT  SIZECODESMD: 1005  (hidden comment: C)
C309  VAL1: 100nF(K)  VAL2: 25V  SIZECODESMD: 1005  (hidden comment: C)
C310  VAL1: 100nF(K)  VAL2: 25V  SIZECODESMD: 1005  (hidden comment: C)
C311  VAL1: 1nF(K)  VAL2: 50V  SIZECODESMD: 1005  (hidden comment: C)
C351  VAL1: 100nF(K)  VAL2: 25V  SIZECODESMD: 1005  (hidden comment: C)
D302  USERCOMPTEXT3: TOSHIBA  VAL3: XCUZ5V6  (hidden comment: ZenerDiode_USC-01)
D303  USERCOMPTEXT3: TOSHIBA  VAL3: 1SS352  (hidden comment: D)
D304  USERCOMPTEXT3: TOSHIBA  VAL3: 1SS405  (hidden comment: D)
D305  USERCOMPTEXT3: TOSHIBA  VAL3: 1SS405  (hidden comment: D)
D306  USERCOMPTEXT3: TOSHIBA  VAL3: 1SS405  (hidden comment: D)
DP301  COMPCOMMENT: Vref_ACIN  USERCOMPTEXT1: ]1.5mm  (hidden comment: TP)
DP302  COMPCOMMENT: Vref_C51  USERCOMPTEXT1: ]1.5mm  (hidden comment: TP)
DP303  USERCOMPTEXT1: ]1.5mm  (hidden comment: TP)
DP304  USERCOMPTEXT1: ]1.5mm  (hidden comment: TP)
IC301  VAL3: NJU7704F3-42A(TE1)  (hidden comment: L7704)
IC302  VAL3: NJU7704F3-42A(TE1)  (hidden comment: L7704)
IC303  VAL3: TLP385(BLL  USERCOMPTEXT3: TOSHIBA  (hidden comment: TLP385)
IC304  USERCOMPTEXT3: TOSHIBA  (hidden comment: DCL540C01)
Q301  USERCOMPTEXT3: TOSHIBA  VAL3: SSM3K15AMFV  (hidden comment: MFNN)
Q302  USERCOMPTEXT3: TOSHIBA  VAL3: SSM3K15AMFV  (hidden comment: MFNN)
Q303  USERCOMPTEXT3: TOSHIBA  VAL3: SSM3K15AMFV  (hidden comment: MFNN)
Q351  USERCOMPTEXT3: TOSHIBA  VAL3: SSM3K15AMFV  (hidden comment: MFNN)
R301  VAL1: 1M(J)  SIZECODESMD: 3216  (hidden comment: R)
R302  VAL1: 1M(J)  SIZECODESMD: 3216  (hidden comment: R)
R303  VAL1: 1M(J)  SIZECODESMD: 3216  (hidden comment: R)
R304  VAL1: 1M(J)  SIZECODESMD: 3216  (hidden comment: R)
R305  VAL1: 180K(J)  SIZECODESMD: 1005  (hidden comment: R)
R306  VAL1: 33K  SIZECODESMD: 1005  (hidden comment: R)
R307  VAL1: 1M(J)  SIZECODESMD: 1005  (hidden comment: R)
R308  VAL1: 10(J)  SIZECODESMD: 1005  (hidden comment: R)
R309  VAL1: 1M(J)  SIZECODESMD: 3216  (hidden comment: R)
R310  VAL1: 1M(J)  SIZECODESMD: 3216  (hidden comment: R)
R311  VAL1: 1M(J)  SIZECODESMD: 3216  (hidden comment: R)
R312  VAL1: 47K(J)  SIZECODESMD: 1005  (hidden comment: R)
R313  VAL1: 0  SIZECODESMD: 1005  (hidden comment: R)
R314  VAL1: 22K(J)  SIZECODESMD: 1005  (hidden comment: R)
R315  VAL1: 22K(J)  SIZECODESMD: 1005  (hidden comment: R)
R316  VAL1: 3.3K(J)  SIZECODESMD: 2012  (hidden comment: R)
R317  VAL1: 1.2K(J)  SIZECODESMD: 1005  (hidden comment: R)
R318  VAL1: 22K(J)  SIZECODESMD: 1005  (hidden comment: R)
R319  VAL1: 22K(J)  SIZECODESMD: 1005  (hidden comment: R)
R320  VAL1: 22K(J)  SIZECODESMD: 1005  (hidden comment: R)
R321  VAL1: 22K(J)  SIZECODESMD: 1005  (hidden comment: R)
R322  VAL1: 22K(J)  SIZECODESMD: 1005  (hidden comment: R)
R323  VAL1: 22K(J)  SIZECODESMD: 1005  (hidden comment: R)
R351  VAL1: 22K(J)  SIZECODESMD: 1005  (hidden comment: R)
R352  VAL1: 22K(J)  SIZECODESMD: 1005  (hidden comment: R)
R353  VAL1: 10(J)  SIZECODESMD: 1005  (hidden comment: R)
R354  VAL1: 1K(J)  SIZECODESMD: 1005  (hidden comment: R)
R355  VAL1: 4.7K(J)  SIZECODESMD: 1005  (hidden comment: R)
R356  VAL1: 2.2K(J)  SIZECODESMD: 1005  (hidden comment: R)
R357  VAL1: 1K(J)  SIZECODESMD: 1005  (hidden comment: R)
R358  VAL1: 4.7K(J)  SIZECODESMD: 1005  (hidden comment: R)
R359  VAL1: 2.2K(J)  SIZECODESMD: 1005  (hidden comment: R)
R360  VAL1: 1K(J)  SIZECODESMD: 1005  (hidden comment: R)
R361  VAL1: 4.7K(J)  SIZECODESMD: 1005  (hidden comment: R)
R362  VAL1: 2.2K(J)  SIZECODESMD: 1005  (hidden comment: R)
R363  VAL1: 1K(J)  SIZECODESMD: 1005  (hidden comment: R)
R364  VAL1: 4.7K(J)  SIZECODESMD: 1005  (hidden comment: R)
R365  VAL1: 2.2K(J)  SIZECODESMD: 1005  (hidden comment: R)
U?#7  DATE: 2026/08/07  DRAWINGNUMBER: RD250-SCHEMATIC-01  TITLE: 1.6kW 48V Output Telecomunication / Equipment Power Supply(Upgraded)  FUNCTION: Isolator & Detection Circuit  SHEETNUMBER: 7/8  REVISION: 01  (hidden comment: WAKU_A3_TDSC_PSDEV_LOCAL)

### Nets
LGND: C351.1 IC304.2 IC304.8 Q351.S R352.1 R356.1 R359.1 R362.1 R365.1
PN: C301.1 C302.1 C303.1 C304.1 C305.1 C306.1 C307.1 C308.1 C309.1 C310.1 C311.1 D302.A DP304.1 IC301.2 IC302.2 IC304.9 IC304.15 Q301.S Q302.S Q303.S R306.1 R312.1 R315.1 R317.1 R319.1 R321.1 R323.1
VCC5R0_1: C309.2 IC304.16
VCC5R0_2: C351.2 IC304.1
VCC12R0_1: R314.2 R316.2 R318.2 R320.2 R322.2
VCC12R0_2: IC303.6
ACIN: C301.2 R301.1 ; off-sheet ACIN
OUTA1: IC304.14 ; off-sheet OUTA1
OUTA2: R355.2 ; off-sheet OUTA2
OUTB1: IC304.13 ; off-sheet OUTB1
OUTB2: R358.2 ; off-sheet OUTB2
OUTC1: IC304.12 ; off-sheet OUTC1
OUTC2: R361.2 ; off-sheet OUTC2
OUTD1: IC304.11 ; off-sheet OUTD1
OUTD2: R364.2 ; off-sheet OUTD2
PFC_OFF: R308.1 ; off-sheet PFC_OFF
PFC_OUT: R309.1 ; off-sheet PFC_OUT
RY_OFF: C311.2 D303.C D304.C IC301.4 Q302.G ; off-sheet RY_OFF
SIG00772: R363.1 R364.1 R365.2
SIG00774: IC304.6 R363.2
SIG00777: IC304.3 R354.2
SIG00781: R360.1 R361.1 R362.2
SIG00783: IC304.4 R357.2
SIG00789: R357.1 R358.1 R359.2
SIG00791: IC304.5 R360.2
SIG00794: R354.1 R355.1 R356.2
SIG00797: C310.2 D306.C DP302.1 IC302.5 R312.2 R313.1
SIG00799: IC303.4 R351.2
SIG007100: C304.2 C305.2 IC301.1
SIG007101: IC303.3 R317.2
SIG007102: D304.A R308.2
SIG007103: IC303.1 Q301.D R316.1
SIG007104: C303.2 IC301.3
SIG007105: Q351.G R351.1 R352.2
SIG007106: D303.A R307.2
SIG007109: R305.1 R306.2
SIG007110: R310.2 R311.1
SIG007111: R303.2 R304.1
SIG007112: C306.2 DP303.1 IC302.3 Q303.D
SIG007115: R311.2 R313.2
SIG007116: C307.2 C308.2 IC302.1
SIG007118: Q351.D R353.1
SIG007120: R309.2 R310.1
SIG007121: R301.2 R302.1
SIG007122: R302.2 R303.1
SIG007123: C302.2 D302.C D305.C DP301.1 IC301.5 R304.2 R305.2 R307.1
SIG007124: IC302.4 Q301.G R314.1 R315.2
SIG007125: Q302.D Q303.G R318.1 R319.2
SIG007126: D305.A R320.1 R321.2
SIG007127: D306.A R322.1 R323.2
SS/EN: R353.2 ; off-sheet SS/EN

Not connected (* = marked no-connect by the designer): IC304 7 10

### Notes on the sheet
- UV_ON=86Vac
  UV_OFF=77Vac
- Primary
- Secondary
- UVLO=275V
- Input Voltage Monitoring
- VINAUVLOAH
  VINAUVLOAL
- VPFC_OUTAUVLOAH
  VPFC_OUTAUVLOAL
- delay=300ms
- PFC Output Voltage
- delay=500ms

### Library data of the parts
C301 = C_Dup1: OriginalSymbolOrigin: (2540,7620); COMP: PRT_46; MAXGCOUNT: 1; SAVECOUNT: 0
C302 C305 C309 C310 C351 = C_Dup1: SQ_PART_MODEL: CON_100N; OriginalSymbolOrigin: (2540,7620); COMP: PRT_52; MAXGCOUNT: 1; ADSCNVFLAG: ON; ADSCOMPONENTNAME: C_1005; SAVECOUNT: 0
C303 C304 C306-C308 C311 = C_Dup1: as C251-C255 on sheet 5
D302 = ZENERDIODE_USC-01: SAVEAREA0: -4630,-153,17114,13055; TIME: 14:49:55; UPDATEUSER: t4887876; UPDATETIME: 08:23:49; SAVECOUNT: 9; COMP: ZenerDiode_USC_01; OriginalSymbolOrigin: (5080,5080); MAXGCOUNT: 1; ADSCNVFLAG: ON; ADSCOMPONENTNAME: D_ZD
D303 = D_Dup1: SAVEAREA0: -225,-91,12804,7836; SAVECOUNT: 3; TIME: 14:49:55; UPDATEUSER: 19870035; UPDATETIME: 14:20:16; OriginalSymbolOrigin: (5080,5080); USERCOMPTEXT2: 80V,0.1A; COMP: PRT_27; MAXGCOUNT: 1
D304-D306 = D_Dup1: SAVEAREA0: -225,-91,12804,7836; SAVECOUNT: 3; TIME: 14:49:55; UPDATEUSER: 19870035; UPDATETIME: 14:20:16; OriginalSymbolOrigin: (5080,5080)
DP301-DP303 = TP: as DP258 on sheet 5
DP304 = TP: TIME: 16:12:21; UPDATEUSER: fukuda-y; UPDATETIME: 16:18:11; SAVECOUNT: 2; SAVEAREA0: -242,-92,12810,7836; OriginalSymbolOrigin: (0,7620); COMPCOMMENT: PN; COMP: DTP815
IC301 IC302 = L7704: SAVECOUNT: 23; SAVEAREA0: -14253,-557,65080,48696; TIME: 18:10:57; UPDATEUSER: 19990028; UPDATETIME: 10:41:32; OriginalSymbolOrigin: (7620,45720); MAXGCOUNT: 1; COMP: GDM470001845; ADSCNVFLAG: ON; FUNCTION: OTHER
IC303 = TLP385: TIME: 18:37:26; UPDATEUSER: t4887876; UPDATETIME: 18:41:04; SAVECOUNT: 3; OriginalSymbolOrigin: (5080,17780); GATENO: 1; ADSCNVFLAG: ON
IC304 = DCL540C01: TIME: 11:12:35; UPDATEUSER: t6860224; UPDATETIME: 11:46:18; SAVECOUNT: 6; SAVEAREA0: -81052,-32740,106905,52903; OriginalSymbolOrigin: (5080,27940); MAXGCOUNT: 1; FUNCTION: FXD
Q301-Q303 Q351 = MFNN: SAVECOUNT: 25; SAVEAREA0: -2884,-274,25430,18334; TIME: 08:01:03; UPDATEUSER: sato-yr; UPDATETIME: 13:42:20; OriginalSymbolOrigin: (2540,17780); MAXGCOUNT: 1; COMP: GDM410000663; ADSCNVFLAG: ON; ADSCOMPONENTNAME: Q_MFNN
R301-R304 R309-R311 = R_Dup1: VAL2: 250mW; OriginalSymbolOrigin: (5080,5080); COMP: PRT_5; CHIPSIZE: 1608; MAXGCOUNT: 1; SAVECOUNT: 0
R305-R308 R312 R314 R315 R317-R323 R351-R365 = R_Dup1: as R253 on sheet 5
R313 = R_Dup1: VAL2: 63mW; OriginalSymbolOrigin: (5080,5080); MAXGCOUNT: 1; COMP: GDM010004481; CHIPSIZE: 1608
R316 = R_Dup1: SQ_PART_MODEL: RES_4.87K; VAL2: 250mW; OriginalSymbolOrigin: (5080,5080); COMP: R2012; CHIPSIZE: 1608; MAXGCOUNT: 1; ADSCNVFLAG: ON; ADSCOMPONENTNAME: R_3216; SAVECOUNT: 0
U?#7 = WAKU_A3_TDSC_PSDEV_LOCAL: PLOTTIME: HH:MM; SAVEAREA0: -311037,-554865,914355,115662; TIME: 16:14:05; UPDATEUSER: t5459927; UPDATETIME: 11:54:52; SAVECOUNT: 3; ZONEOFFSETX: 36; ZONEOFFSETY: -24; OriginalSymbolOrigin: (0,434340); SHTSAVECOUNT: 146; PAGENUMBER: 7; DESIGNED: TOSHIBA

## Sheet 8.SchDoc
size 599 x 434 mm
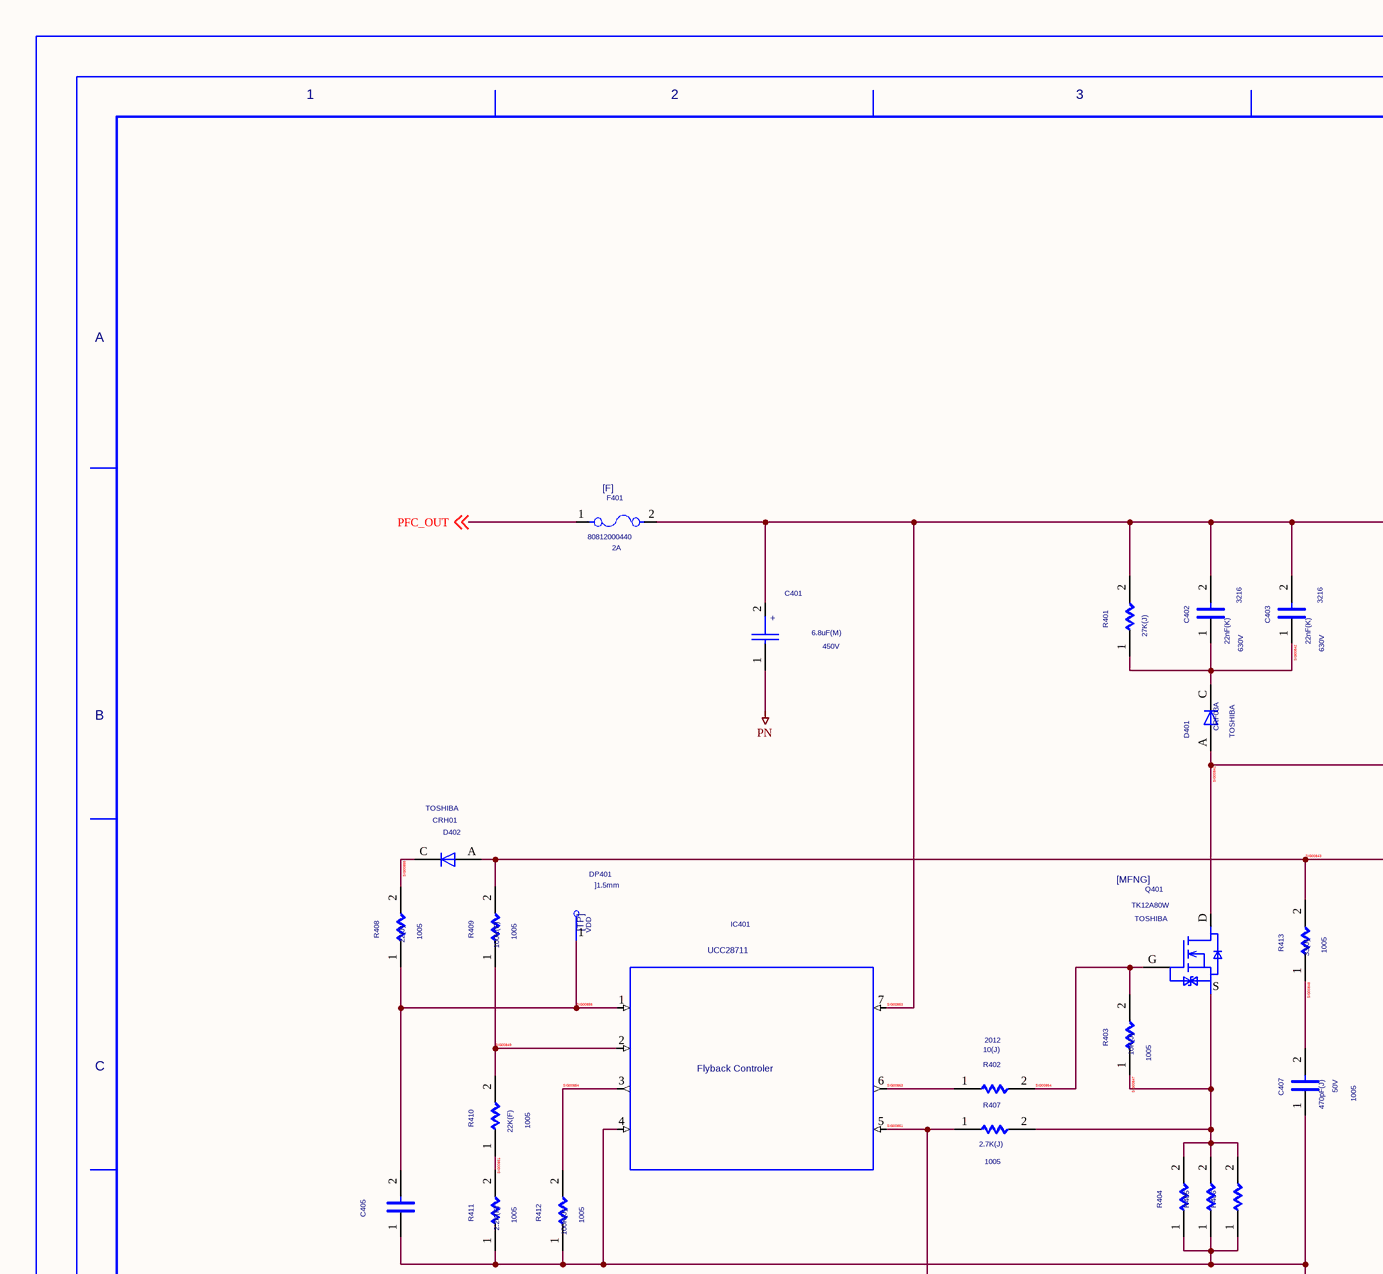
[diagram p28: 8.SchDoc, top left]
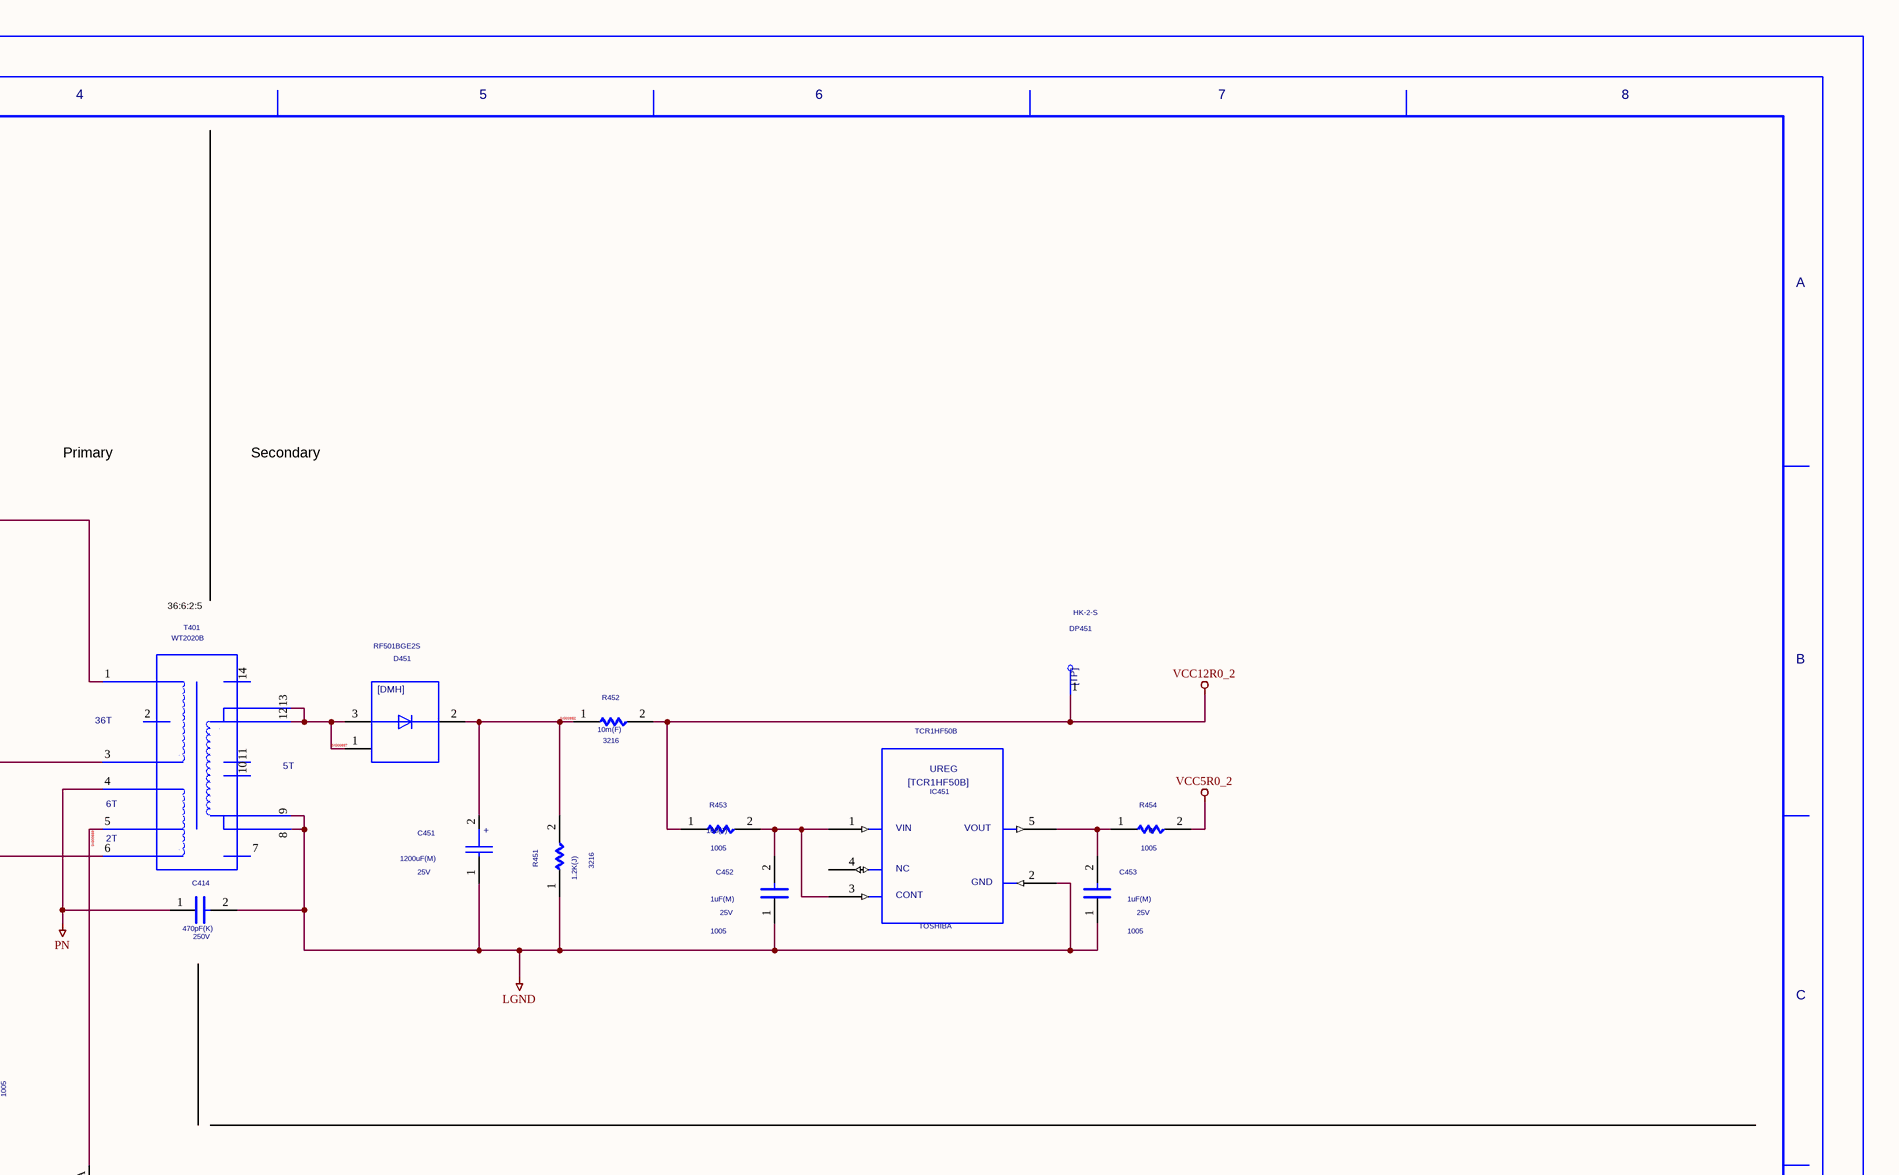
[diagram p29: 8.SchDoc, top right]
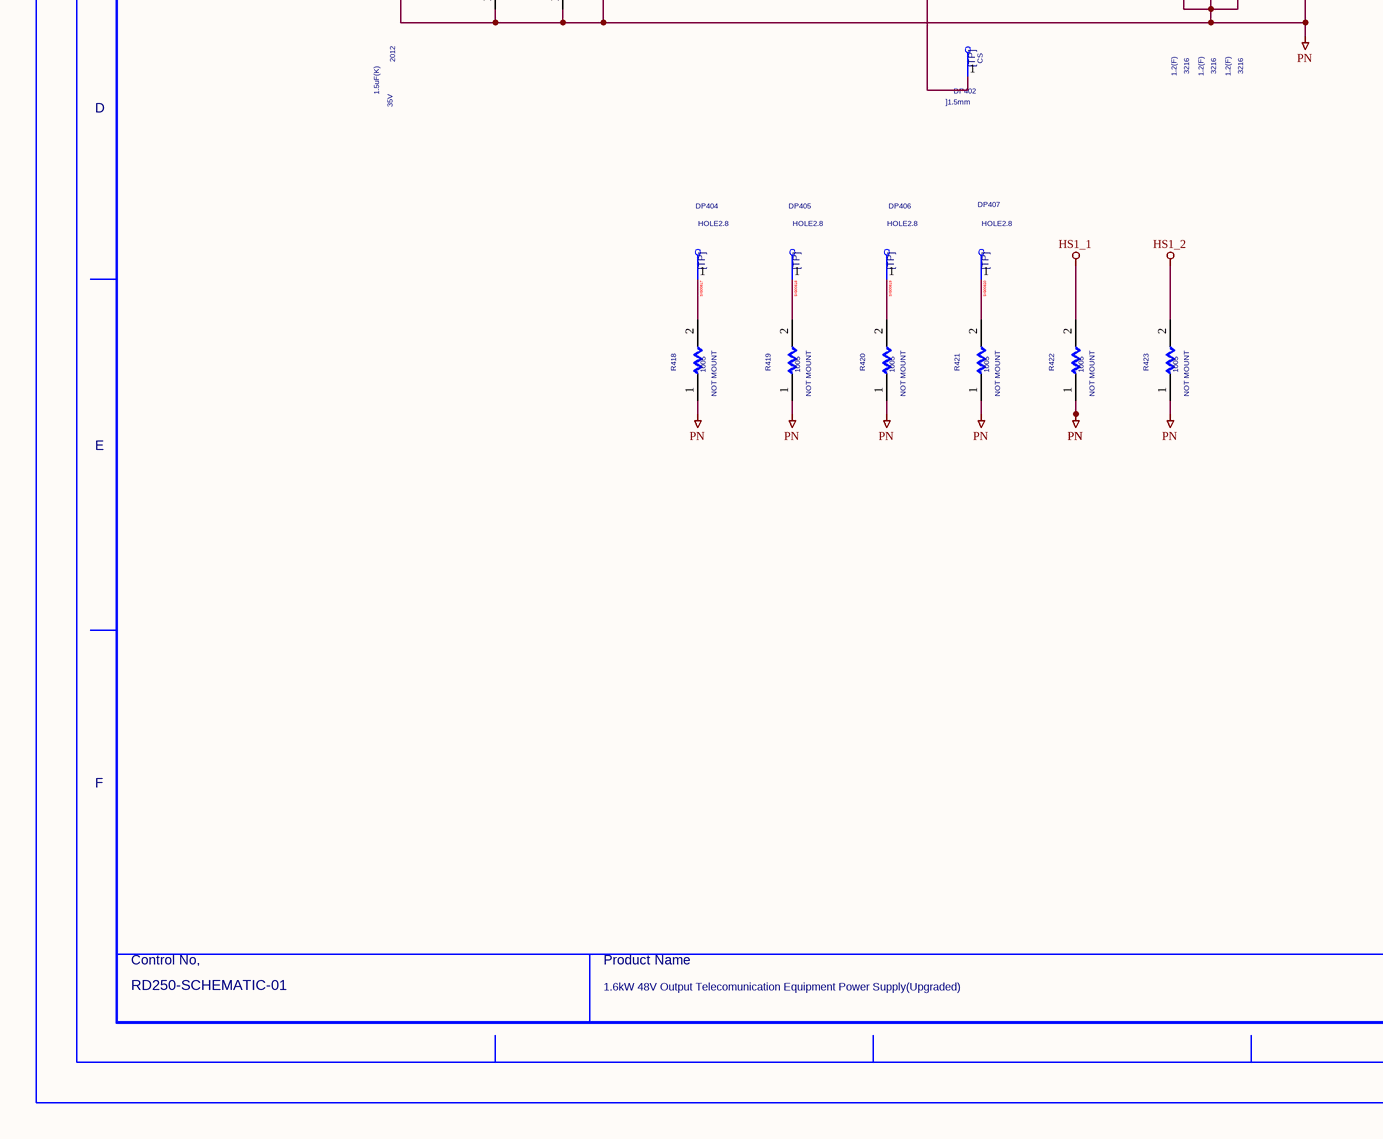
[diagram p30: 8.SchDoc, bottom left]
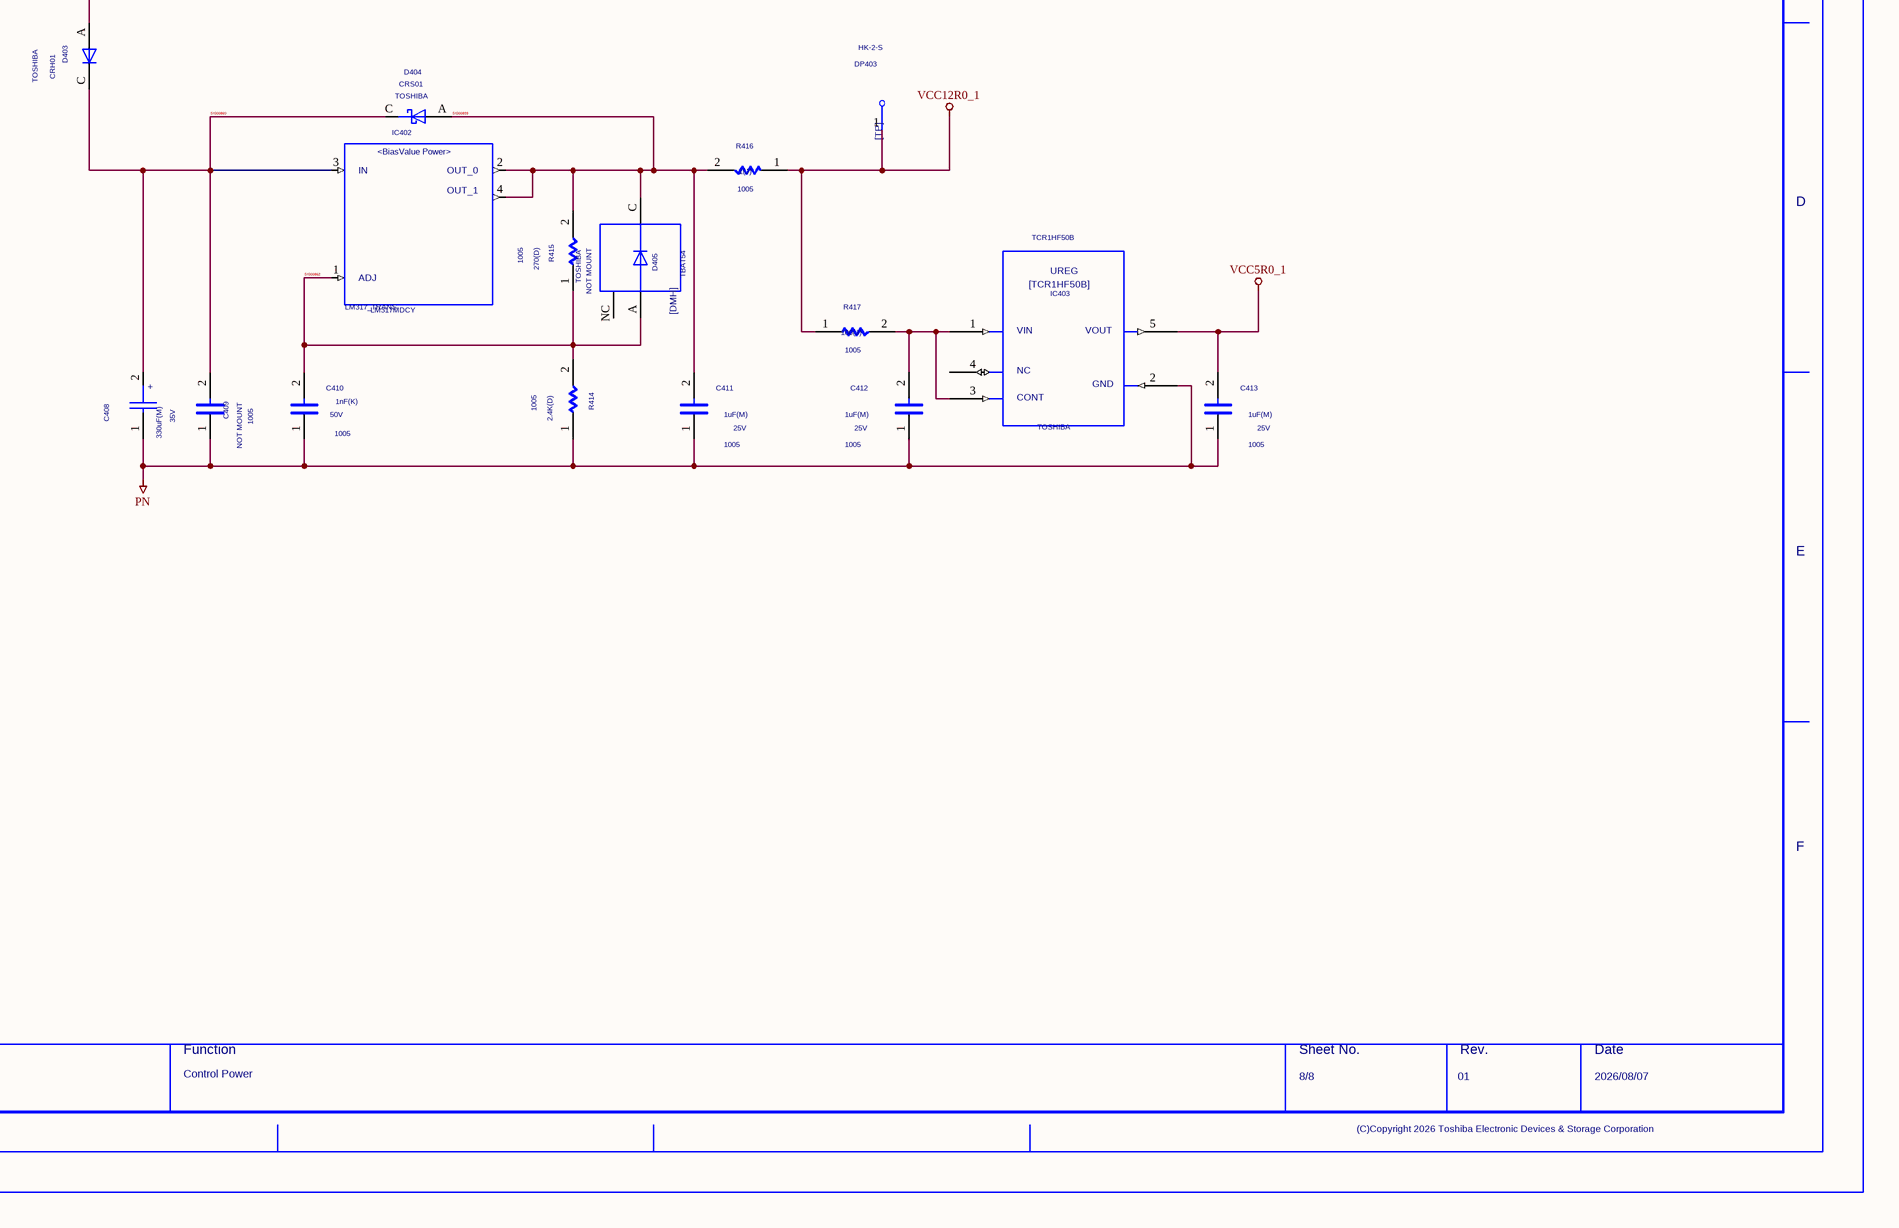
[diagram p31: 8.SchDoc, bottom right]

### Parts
(Parts that share a designator on the sheet are numbered #1, #2 ... from top to bottom, then left to right.)
C401  VAL1: 6.8uF(M)  VAL2: 450V  (hidden comment: CP)
C402  VAL1: 22nF(K)  VAL2: 630V  SIZECODESMD: 3216  (hidden comment: C)
C403  VAL1: 22nF(K)  VAL2: 630V  SIZECODESMD: 3216  (hidden comment: C)
C405  VAL1: 1.5uF(K)  VAL2: 35V  SIZECODESMD: 2012  (hidden comment: GRM21BC71E106KE01)
C407  VAL1: 470pF(J)  VAL2: 50V  SIZECODESMD: 1005  (hidden comment: C)
C408  VAL1: 330uF(M)  VAL2: 35V  (hidden comment: CP)
C409  NOTMOUNT: NOT MOUNT  SIZECODESMD: 1005  (hidden comment: C)
C410  VAL1: 1nF(K)  VAL2: 50V  SIZECODESMD: 1005  (hidden comment: C)
C411  VAL1: 1uF(M)  VAL2: 25V  SIZECODESMD: 1005  (hidden comment: C)
C412  VAL1: 1uF(M)  VAL2: 25V  SIZECODESMD: 1005  (hidden comment: C)
C413  VAL1: 1uF(M)  VAL2: 25V  SIZECODESMD: 1005  (hidden comment: C)
C414  VAL1: 470pF(K)  VAL2: 250V  (hidden comment: C)
C451  VAL1: 1200uF(M)  VAL2: 25V  (hidden comment: CP)
C452  VAL1: 1uF(M)  VAL2: 25V  SIZECODESMD: 1005  (hidden comment: C)
C453  VAL1: 1uF(M)  VAL2: 25V  SIZECODESMD: 1005  (hidden comment: C)
D401  USERCOMPTEXT3: TOSHIBA  VAL3: CRF03A  (hidden comment: D)
D402  USERCOMPTEXT3: TOSHIBA  VAL3: CRH01  (hidden comment: D)
D403  USERCOMPTEXT3: TOSHIBA  VAL3: CRH01  (hidden comment: D)
D404  USERCOMPTEXT3: TOSHIBA  VAL3: CRS01  (hidden comment: SBD)
D405  NOTMOUNT: NOT MOUNT  USERCOMPTEXT3: TOSHIBA  VAL3: TBAT54  (hidden comment: DMH)
D451  RF501BGE2S
DP401  COMPCOMMENT: VDD  USERCOMPTEXT1: ]1.5mm  (hidden comment: TP)
DP402  COMPCOMMENT: CS  USERCOMPTEXT1: ]1.5mm  (hidden comment: TP)
DP403  VAL3: HK-2-S  (hidden comment: TP)
DP404  VAL3: HOLE2.8  (hidden comment: TP)
DP405  VAL3: HOLE2.8  (hidden comment: TP)
DP406  VAL3: HOLE2.8  (hidden comment: TP)
DP407  VAL3: HOLE2.8  (hidden comment: TP)
DP451  VAL3: HK-2-S  (hidden comment: TP)
F401  VAL1: 2A  VAL3: 80812000440  (hidden comment: F)
IC401  UCC28711
IC402  LM317_TRANS  [DCY0004A_N]
IC403  USERCOMPTEXT3: TOSHIBA  (hidden comment: TCR1HF50B)
IC451  USERCOMPTEXT3: TOSHIBA  (hidden comment: TCR1HF50B)
Q401  USERCOMPTEXT3: TOSHIBA  VAL3: TK12A80W  (hidden comment: MFNF)
R401  VAL1: 27K(J)  (hidden comment: R)
R402  VAL1: 10(J)  SIZECODESMD: 2012  (hidden comment: R)
R403  VAL1: 10K(J)  SIZECODESMD: 1005  (hidden comment: R)
R404  VAL1: 1.2(F)  SIZECODESMD: 3216  (hidden comment: R)
R405  VAL1: 1.2(F)  SIZECODESMD: 3216  (hidden comment: R)
R406  VAL1: 1.2(F)  SIZECODESMD: 3216  (hidden comment: R)
R407  VAL1: 2.7K(J)  SIZECODESMD: 1005  (hidden comment: R)
R408  VAL1: 22(J)  SIZECODESMD: 1005  (hidden comment: R)
R409  VAL1: 100K(F)  SIZECODESMD: 1005  (hidden comment: R)
R410  VAL1: 22K(F)  SIZECODESMD: 1005  (hidden comment: R)
R411  VAL1: 2.2K(F)  SIZECODESMD: 1005  (hidden comment: R)
R412  VAL1: 100K(J)  SIZECODESMD: 1005  (hidden comment: R)
R413  VAL1: 33(J)  SIZECODESMD: 1005  (hidden comment: R)
R414  VAL1: 2.4K(D)  SIZECODESMD: 1005  (hidden comment: R)
R415  VAL1: 270(D)  SIZECODESMD: 1005  (hidden comment: R)
R416  VAL1: 1(J)  SIZECODESMD: 1005  (hidden comment: R)
R417  VAL1: 100(J)  SIZECODESMD: 1005  (hidden comment: R)
R418  NOTMOUNT: NOT MOUNT  SIZECODESMD: 1005  (hidden comment: R)
R419  NOTMOUNT: NOT MOUNT  SIZECODESMD: 1005  (hidden comment: R)
R420  NOTMOUNT: NOT MOUNT  SIZECODESMD: 1005  (hidden comment: R)
R421  NOTMOUNT: NOT MOUNT  SIZECODESMD: 1005  (hidden comment: R)
R422  NOTMOUNT: NOT MOUNT  SIZECODESMD: 1005  (hidden comment: R)
R423  NOTMOUNT: NOT MOUNT  SIZECODESMD: 1005  (hidden comment: R)
R451  VAL1: 1.2K(J)  SIZECODESMD: 3216  (hidden comment: R)
R452  USERCOMPTEXT1: 10m(F)  SIZECODESMD: 3216  (hidden comment: R)
R453  VAL1: 100(J)  SIZECODESMD: 1005  (hidden comment: R)
R454  VAL1: 0  SIZECODESMD: 1005  (hidden comment: R)
T401  T3_12V67A  (value not drawn)
U?#8  DATE: 2026/08/07  DRAWINGNUMBER: RD250-SCHEMATIC-01  TITLE: 1.6kW 48V Output Telecomunication / Equipment Power Supply(Upgraded)  FUNCTION: Control Power  SHEETNUMBER: 8/8  REVISION: 01  (hidden comment: WAKU_A3_TDSC_PSDEV_LOCAL)

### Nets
HS1_1: R422.2
HS1_2: R423.2
LGND: C414.2 C451.1 C452.1 C453.1 IC451.2 R451.1 T401.8 T401.9
PN: C401.1 C405.1 C407.1 C408.1 C409.1 C410.1 C411.1 C412.1 C413.1 C414.1 IC401.4 IC403.2 R404.1 R405.1 R406.1 R411.1 R412.1 R414.1 R418.1 R419.1 R420.1 R421.1 R422.1 R423.1 T401.4
VCC5R0_1: C413.2 IC403.5
VCC5R0_2: R454.2
VCC12R0_1: DP403.1 R416.1 R417.1
VCC12R0_2: DP451.1 R452.2 R453.1
PFC_OUT: F401.1 ; off-sheet PFC_OUT
SIG00817: DP404.1 R418.2
SIG00818: DP405.1 R419.2
SIG00819: DP406.1 R420.2
SIG00820: DP407.1 R421.2
SIG00823: C453.2 IC451.5 R454.1
SIG00826: C452.2 IC451.1 IC451.3 R453.2
SIG00837: D451.1 D451.3 T401.12 T401.13
SIG00839: C411.2 D404.A D405.C IC402.2 IC402.4 R415.2 R416.2
SIG00841: D401.A Q401.D T401.3
SIG00842: C402.1 C403.1 D401.C R401.1
SIG00843: D402.A R409.2 R413.2 T401.6
SIG00847: Q401.S R403.1 R404.2 R405.2 R406.2 R407.2
SIG00848: C407.2 R413.1
SIG00849: IC401.2 R409.1 R410.2
SIG00851: DP402.1 IC401.5 R407.1
SIG00852: C451.2 D451.2 R451.2 R452.1
SIG00853: C401.2 C402.2 C403.2 F401.2 IC401.7 R401.2 T401.1
SIG00854: IC401.3 R412.2
SIG00855: D402.C R408.2
SIG00856: C405.2 DP401.1 IC401.1 R408.1
SIG00858: C412.2 IC403.1 IC403.3 R417.2
SIG00859: D403.A T401.5
SIG00860: C408.2 C409.2 D403.C D404.C IC402.3
SIG00861: R410.1 R411.2
SIG00862: C410.2 D405.A IC402.1 R414.2 R415.1
SIG00863: IC401.6 R402.1
SIG00864: Q401.G R402.2 R403.2

Not connected (* = marked no-connect by the designer): D405 NC; IC403 4; IC451 4; T401 2 7 10 11 14

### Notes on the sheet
- Primary
- Secondary
- 36:6:2:5

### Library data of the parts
C401 = CP: SAVEAREA0: -1450,-153,20294,13055; SAVECOUNT: 52; TIME: 15:02:55; UPDATEUSER: fukuda-y; UPDATETIME: 16:13:42; OriginalSymbolOrigin: (2540,10160); VAL3: EKXJ451ELL6R8MJ16S; COMP: PRT_3; CHIPSIZE: D10xL22; MAXGCOUNT: 1; SIZECODESMD: DIP
C402 C403 = C: OriginalSymbolOrigin: (2540,7620); COMP: PRT_46; SAVECOUNT: 0
C405 = GRM21BC71E106KE01: as C509-C512 on sheet 6
C407 C409 C410 = C_Dup1: OriginalSymbolOrigin: (2540,7620); COMP: PRT_52; SAVECOUNT: 0
C408 = CP: SAVEAREA0: -1450,-153,20294,13055; SAVECOUNT: 52; TIME: 15:02:55; UPDATEUSER: fukuda-y; UPDATETIME: 16:13:42; OriginalSymbolOrigin: (2540,10160); SIZECODESMD: 1010; COMP: EMLA350ARA331MJA0G
C411-C413 C452 C453 = C_Dup1: SQ_PART_MODEL: CON_1U; OriginalSymbolOrigin: (2540,7620); COMP: PRT_52; MAXGCOUNT: 1; ADSCNVFLAG: ON; ADSCOMPONENTNAME: C_1608; SAVECOUNT: 0
C414 = C_Dup1: OriginalSymbolOrigin: (2540,7620); VAL3: DE2B3SA221KA3BT02F; SAVECOUNT: 0
C451 = CP: SAVEAREA0: -1450,-153,20294,13055; SAVECOUNT: 52; TIME: 15:02:55; UPDATEUSER: fukuda-y; UPDATETIME: 16:13:42; OriginalSymbolOrigin: (2540,10160); VAL3: EKZN250ELL122MJ25S; SIZECODESMD: DIP; COMP: PRT_3
D401 = D_Dup1: SAVEAREA0: -225,-91,12804,7836; SAVECOUNT: 3; TIME: 14:49:55; UPDATEUSER: 19870035; UPDATETIME: 14:20:16; OriginalSymbolOrigin: (5080,5080); USERCOMPTEXT2: 600V,0.7A
D402 D403 = D: SAVEAREA0: -225,-91,12804,7836; SAVECOUNT: 3; TIME: 14:49:55; UPDATEUSER: 19870035; UPDATETIME: 14:20:16; OriginalSymbolOrigin: (5080,5080); USERCOMPTEXT2: 200V,1A; MAXGCOUNT: 1; ADSCNVFLAG: ON; ADSCOMPONENTNAME: D_D; COMP: GDM420000387
D404 = SBD: SAVEAREA0: -4630,-153,17114,13055; TIME: 14:49:55; UPDATEUSER: fukuda-y; UPDATETIME: 08:16:22; SAVECOUNT: 9; OriginalSymbolOrigin: (5080,5080); USERCOMPTEXT2: 30V,1A; MAXGCOUNT: 1; COMP: K4200730; ADSCNVFLAG: ON; ADSCOMPONENTNAME: D_SBD
D405 = DMH: SAVEAREA0: -4931,-287,27399,20979; TIME: 08:58:08; UPDATEUSER: kishi-s; UPDATETIME: 09:01:52; SAVECOUNT: 2; OriginalSymbolOrigin: (5080,17780); USERCOMPTEXT2: 30V,0.2A; COMP: PRT_25
D451 = RF501BGE2S: SAVEAREA0: -4931,-287,27399,20979; TIME: 08:58:08; UPDATEUSER: t6860224; UPDATETIME: 11:55:12; SAVECOUNT: 3; OriginalSymbolOrigin: (5080,17780); USERCOMPTEXT3: #%ﾘ%; MAXGCOUNT: 1; COMP: NJM78M05SDL1_TE1; ADSCNVFLAG: ON; ADSCOMPONENTNAME: D_SBDMB
DP401 DP402 = TP: as DP258 on sheet 5
DP403 DP451 = TP: as DP251-DP256 on sheet 5
DP404-DP407 = TP: TIME: 16:12:21; UPDATEUSER: fukuda-y; UPDATETIME: 16:18:11; SAVECOUNT: 2; SAVEAREA0: -242,-92,12810,7836; OriginalSymbolOrigin: (0,7620); COMP: PRT_39; CHIPSIZE: Through Hole
F401 = F: OriginalSymbolOrigin: (2540,5080); SAVECOUNT: 0
IC401 = UCC28711DR: PSPICETEMPLATE: X^@REFDES %CS %VS %CBC %DRV %VDD %GND %HV @MODEL; TIME: 16:40:05; UPDATEUSER: t4887876; UPDATETIME: 09:12:44; SAVECOUNT: 14; SAVEAREA0: -40606,-13411,99691,50516; OriginalSymbolOrigin: (2540,38100)
IC402 = LM317MDCY: ALTERNATE PARTNUMBER: LM317DCY; PARTNUMBER: LM317DCYR; MANUFACTURER: Texas Instruments; PIN_COUNT: 4; SYMBOLCREATER: Altium; DEVICESINPACKAGE: 1; ISHETEROGENEOUS: False; DEVICEDESIGNATOR: A; DEVICENUMBERING: Alpha; PSPICETEMPLATE: X^@REFDES %IN %ADJ %OUT_0 %OUT_1 @MODEL; ORIGINALSYMBOLORIGIN: (2540,30480); COMPTYPE: IC; TIME: 16:40:05; UPDATEUSER: t6860224; UPDATETIME: 16:01:55; SAVECOUNT: 6; SAVEAREA0: -16909,0,49982,30480; FUNCTION: FXD
IC403 IC451 = TCR1HF50B: SAVEAREA0: -444,-3509,43701,41525; TIME: 18:31:00; UPDATEUSER: t6860224; UPDATETIME: 12:58:25; SAVECOUNT: 21; OriginalSymbolOrigin: (7620,35560)
Q401 = MFNG: SAVECOUNT: 11; SAVEAREA0: -7084,-293,21840,15991; OriginalSymbolOrigin: (5080,12700); MAXGCOUNT: 1; ADSCNVFLAG: ON; ADSCOMPONENTNAME: Q_MFNG; PIN NAMES VISIBLE: False; COMP: K4100860; PIN NAMES ROTATE: True
R401 = R: VAL2: 3W; OriginalSymbolOrigin: (5080,5080); VAL3: PR03000202702JAC00; COMP: PRT_54; SIZECODESMD: TH; SAVECOUNT: 0
R402 = R: VAL2: 250mW; OriginalSymbolOrigin: (5080,5080); COMP: R2012; SAVECOUNT: 0
R403 R408-R413 = R: VAL2: 63mW; OriginalSymbolOrigin: (5080,5080); MAXGCOUNT: 1; COMP: GDM010004481; SAVECOUNT: 0
R404-R406 = R: VAL2: 250mW; OriginalSymbolOrigin: (5080,5080); COMP: R3216; SAVECOUNT: 0
R407 = R: VAL2: 63mW; OriginalSymbolOrigin: (5080,5080); COMP: GDM010004481; SAVECOUNT: 0
R414 R415 = R_Dup1: VAL2: 63mW; OriginalSymbolOrigin: (5080,5080); MAXGCOUNT: 1; COMP: GDM010004481; SAVECOUNT: 0
R416 = R_Dup1: SQ_PART_MODEL: RES_0; VAL2: 63mW; OriginalSymbolOrigin: (5080,5080); COMP: GDM010004481; CHIPSIZE: 1608; MAXGCOUNT: 1; ADSCNVFLAG: ON; ADSCOMPONENTNAME: R_1005; SAVECOUNT: 0
R417 R453 = R_Dup1: as R253 on sheet 5
R418-R423 = R_Dup1: SQ_PART_MODEL: RES_0; OriginalSymbolOrigin: (5080,5080); COMP: GDM010004481; CHIPSIZE: 1608; MAXGCOUNT: 1; ADSCNVFLAG: ON; ADSCOMPONENTNAME: R_1005; SAVECOUNT: 0
R451 R452 = R: VAL2: 250mW; OriginalSymbolOrigin: (5080,5080); COMP: PRT_5; SAVECOUNT: 0
R454 = R_Dup1: SQ_PART_MODEL: RES_0; VAL2: 63mW; OriginalSymbolOrigin: (5080,5080); COMP: GDM010004481; CHIPSIZE: 1608; MAXGCOUNT: 1; ADSCNVFLAG: ON; ADSCOMPONENTNAME: R_1005
T401 = WT2020B: UPDATEUSER: t4887876; UPDATETIME: 11:02:48; SAVECOUNT: 21; TIME: 16:40:06; SAVEAREA0: -85659,-25353,110804,64166; ORIGINALSYMBOLORIGIN: (0,40640); VAL1: spec = YB-3513A; VAL2: 36:6:2:5
U?#8 = WAKU_A3_TDSC_PSDEV_LOCAL: PLOTTIME: HH:MM; SAVEAREA0: -311037,-554865,914355,115662; TIME: 18:12:27; UPDATEUSER: t5459927; UPDATETIME: 11:24:38; SAVECOUNT: 3; ZONEOFFSETX: 36; ZONEOFFSETY: -24; OriginalSymbolOrigin: (0,434340); SHTSAVECOUNT: 194; PAGENUMBER: 8; DESIGNED: TOSHIBA

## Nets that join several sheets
LGND: 3 (R251.1 T101.3), 4 (68 pins), 5 (28 pins), 6 (17 pins), 7 (9 pins), 8 (8 pins)
PN: 1 (C11.1 Q1.S R5.1 R6.1), 2 (54 pins), 3 (35 pins), 7 (27 pins), 8 (25 pins)
VCC5R0_1: 3 (8 pins), 7 (C309.2 IC304.16), 8 (C413.2 IC403.5)
VCC5R0_2: 7 (C351.2 IC304.1), 8 (R454.2)
VCC12R0_1: 1 (C11.2 D1.C R4.1 RY1.4), 2 (6 pins), 3 (R106.1 R117.1), 7 (5 pins), 8 (DP403.1 R416.1 R417.1)
VCC12R0_2: 4 (R151.1 R201.1), 5 (R260.1), 6 (CN504.1 CN504.2), 7 (IC303.6), 8 (DP451.1 R452.2 R453.1)
ACIN: 2 (D51.C D52.C), 7 (C301.2 R301.1)
CONN002: 3 (7 pins), 4 (CN101.1 CN104.1)
CONN003: 3 (D108.A D109.C L101.2), 4 (CN103.1 CN106.1)
CONN004: 4 (17 pins), 5 (R287.2), 6 (16 pins)
CS: 3 (D251.C), 5 (R282.2 R284.2)
OUTA1: 3 (R104.2), 7 (IC304.14)
OUTA2: 5 (DP251.1 IC251.22), 7 (R355.2)
OUTB1: 3 (R103.2), 7 (IC304.13)
OUTB2: 5 (DP252.1 IC251.21), 7 (R358.2)
OUTC1: 3 (R115.2), 7 (IC304.12)
OUTC2: 5 (DP253.1 IC251.20), 7 (R361.2)
OUTD1: 3 (R114.2), 7 (IC304.11)
OUTD2: 5 (DP254.1 IC251.19), 7 (R364.2)
OUTE: 4 (R164.1 R214.1), 5 (DP255.1 IC251.18)
OUTF: 4 (R165.1 R215.1), 5 (DP256.1 IC251.17)
PFC_OFF: 2 (C66.2 DP61.1 IC52.18), 7 (R308.1)
PFC_OUT: 2 (9 pins), 3 (R101.2 T101.2), 7 (R309.1), 8 (F401.1)
RY_OFF: 1 (R4.2 R7.1), 7 (5 pins)
SIG6: 1 (C8.2 C9.1 L2.3), 2 (D52.A D54.A D55.3 L52.1)
SIG8: 1 (C9.2 R3.2 RY1.2), 2 (D51.A D53.A D55.2 L51.1)
SS/EN: 5 (C251.2 IC251.5 R252.2), 7 (R353.2)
